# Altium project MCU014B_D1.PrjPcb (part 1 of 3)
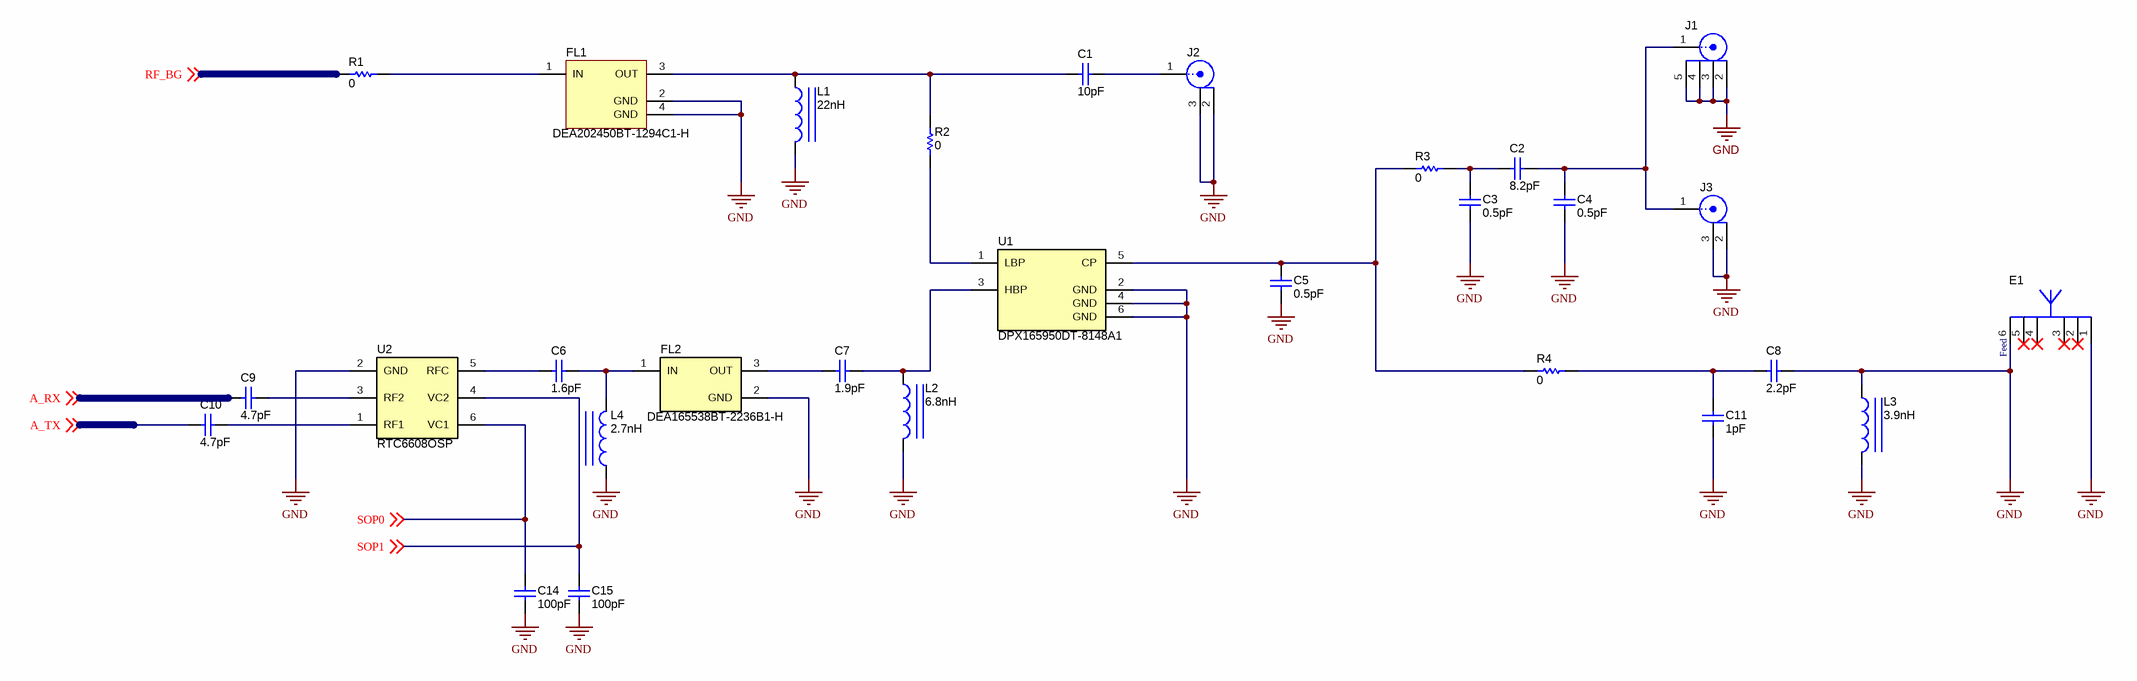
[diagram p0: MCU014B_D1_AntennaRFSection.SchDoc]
CopyrightYear: 2018; DrawnBy: Vince Rodriguez; PCB_Layout: Tessolve; PCB_Rev: B; PRJ_Customer: Public Release; PRJ_Engineer: Vince Rodriguez; PRJ_Number: MCU014; PRJ_Title: LAUNCHXL-CC3235(S & SF); SCH_Rev: B; TechSupport: http://www.ti.com/support; TID: N/A
7 sheets, 374 parts. Net scope: global (net labels, ports and power ports of the same name join across sheets).
Board file: MCU014B_D1.PcbDoc
Sheets:
  MCU014B_D1_AntennaRFSection.SchDoc
  MCU014B_D1_CoverSheet.SchDoc
  MCU014B_D1_EmulationCircuit.SchDoc
  MCU014B_D1_EVM_Hardware.SchDoc
  MCU014B_D1_EngineArea.SchDoc
  MCU014B_D1_HostInterface_ADC.SchDoc
  MCU014B_D1_PowerLedsSwitchSensors.SchDoc

## Sheet MCU014B_D1_AntennaRFSection.SchDoc
size 431 x 279 mm; Date: Not shown in title block; ApprovedBy: Not shown in title block; CheckedBy: Not shown in title block; Author: Not shown in title block; CompanyName: Not shown in title block; DrawnBy: Vince Rodriguez; Engineer: Vince Rodriguez; Organization: Not shown in title block; Address1: Not shown in title block; Address2: Not shown in title block; Address3: Not shown in title block; Address4: Not shown in title block; DocumentNumber: 6; Revision: Use project parameter SCH_Rev; SheetNumber: 6; SheetTotal: 7; PageSetup: Record=PageOptions¦CenterHorizontal=True¦CenterVertical=True¦PrintScale=1.00¦XCorrection=1.00¦YCorrection=1.00¦PrintKind=0¦BorderSize=5000000¦LeftOffset=0¦BottomOffset=0¦Orientation=2¦PaperLength=1000¦PaperWidth=1000¦Scale=100¦PaperSource=15¦PrintQuality=600¦MediaType=1¦DitherType=10¦PaperKind=Letter¦PrintScaleMode=1

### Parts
C1  ValueDisplayed: 10pF  [0402S]  (hidden comment: CMP-0006408-2)
C2  ValueDisplayed: 8.2pF  [0402S]  (hidden comment: 0402N8R2C500CT)
C3  ValueDisplayed: 0.5pF  [0402S]  (hidden comment: GJM1555C1HR50BB01J)
C4  ValueDisplayed: 0.5pF  [0402S]  (hidden comment: GJM1555C1HR50BB01J)
C5  ValueDisplayed: 0.5pF  [0402S]  (hidden comment: GJM1555C1HR50BB01J)
C6  ValueDisplayed: 1.6pF  [0201_033]  (hidden comment: GRM0335C1H1R6BA01D)
C7  ValueDisplayed: 1.9pF  [0402S]  (hidden comment: GJM1555C1H1R9WB01D)
C8  ValueDisplayed: 2.2pF  [0402S]  (hidden comment: GJM1555C1H2R2BB01D)
C9  ValueDisplayed: 4.7pF  [0201_033]  (hidden comment: GRM0335C1H4R7BA01D)
C10  ValueDisplayed: 4.7pF  [0201_033]  (hidden comment: GRM0335C1H4R7BA01D)
C11  ValueDisplayed: 1pF  [0402S]  (hidden comment: CMP-0006426-2)
C14  ValueDisplayed: 100pF  [0201]  (hidden comment: CC0201JRNPO8BN101)
C15  ValueDisplayed: 100pF  [0201]  (hidden comment: CC0201JRNPO8BN101)
E1  CMP-0001857-1  [Ethertronics_M830520]  (value not drawn)
FL1  PartNumber: DEA202450BT-1294C1-H  [TDK_DEA202450BT-1294C1-H]  (hidden comment: CMP-0002039-2)
FL2  PartNumber: DEA165538BT-2236B1-H  [TDK_DEA165538BT-2236B1-H]  (hidden comment: CMP-0002038-2)
J1  CMP-0055832-1  [Hustsan_SMA-10V21-TGG]  (value not drawn)
J2  U.FL-R-SMT-1(01)  [CONN_UFL-R-SMT-1]  (value not drawn)
J3  U.FL-R-SMT-1(01)  [CONN_UFL-R-SMT-1]  (value not drawn)
L1  ValueDisplayed: 22nH  [0402S]  (hidden comment: LQG15HZ22NH02D)
L2  ValueDisplayed: 6.8nH  [0402S]  (hidden comment: LQG15HZ6N8H02D)
L3  ValueDisplayed: 3.9nH  [0402S]  (hidden comment: CMP-0058633-2)
L4  ValueDisplayed: 2.7nH  [0402S]  (hidden comment: LQG15WH2N7C02D)
R1  ValueDisplayed: 0  [0201]  (hidden comment: CRCW02010000Z0ED)
R2  ValueDisplayed: 0  [0402S]  (hidden comment: CMP-0026992-2)
R3  ValueDisplayed: 0  [0402S]  (hidden comment: CMP-0026992-2)
R4  ValueDisplayed: 0  [0402S]  (hidden comment: CMP-0026992-2)
U1  PartNumber: DPX165950DT-8148A1  [TDK_DPX165950DT-8148A1]  (hidden comment: CMP-0002040-1)
U2  RTC6608OSP  [Richwave_RTC6608OSP]

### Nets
GND: C3.2 C4.2 C5.2 C8.2 C11.2 C14.2 C15.2 E1.1(Feed) E1.6 FL1.2(GND) FL1.4(GND) FL2.2(GND) J1.2 J1.3 J1.4 J1.5 J2.2 J2.3 J3.2 J3.3 L1.2 L2.2 L3.1 L3.2 L4.1 U1.2(GND) U1.4(GND) U1.6(GND) U2.2(GND)
A_RX: C9.2 ; off-sheet A_RX
A_TX: C10.2 ; off-sheet A_TX
RF_BG: R1.2 ; off-sheet RF_BG
SOP0: C14.1 U2.6(VC1) ; off-sheet SOP0
SOP1: C15.1 U2.4(VC2) ; off-sheet SOP1
NetC1_1: C1.1 FL1.3(OUT) L1.1 R2.2
NetC1_2: C1.2 J2.1
NetC2_1: C2.1 C3.1 R3.2
NetC2_2: C2.2 C4.1 J1.1 J3.1
NetC5_1: C5.1 R3.1 R4.1 U1.5(CP)
NetC6_1: C6.1 FL2.1(IN) L4.2
NetC6_2: C6.2 U2.5(RFC)
NetC7_1: C7.1 FL2.3(OUT)
NetC7_2: C7.2 L2.1 U1.3(HBP)
NetC8_1: C8.1 C11.1 R4.2
NetC9_1: C9.1 U2.3(RF2)
NetC10_1: C10.1 U2.1(RF1)
NetFL1_1: FL1.1(IN) R1.1
NetR2_1: R2.1 U1.1(LBP)

Not connected (* = marked no-connect by the designer): E1 2(GND)* 3(GND)* 4(Feed)* 5*

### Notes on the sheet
- (near E1) Feed

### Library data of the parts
C1 = CMP-0006408-2: CAP, CERM, 10 pF, 50 V, +/- 5%, C0G/NP0, 0402; PartNumber: GRM1555C1H100JA01D; Manufacturer: MuRata; Alternate Manufacturer: ----; Polarized: N; CompType: Capacitor; Value: 10pF; U/M: EA; Value1: Unknown; VDC_V: 50V; TaMin_C: -55°C; TaMax_C: 125°C; Cap_Case: 0402; SizeAreaWB_mm2: 3; SizeZ_mm: 0.6; SizeX_mm: 1; SizeY_mm: 0.5; AEC Category: Q200
C2 = CMP-0085845-1: CAP, CERM, 8.2 pF, 50 V,+/- 3%, C0G/NP0, 0402; Manufacturer: Walsin; Alternate PartNumber: GRM1555C1H8R2CA01D; Alternate Manufacturer: MuRata; Polarized: N; Value: 8.2pF; U/M: EA; VDC_V: 50V; TaMin_C: -55°C; TaMax_C: 125°C; Cap_Case: 0402; SizeArea_mm2: 0.5; SizeAreaWB_mm2: 3; SizeX_mm: 1; SizeZ_mm: 0.6; AEC Category: Q200
C3-C5 = CMP-0080073-1: CAP, CERM, 0.5 pF, 50 V,+/- 20%, C0G/NP0, 0402; Manufacturer: MuRata; Polarized: N; Value: 0.5pF; U/M: EA; VDC_V: 50V; TaMin_C: -55°C; TaMax_C: 125°C; Cap_Case: 0402; Green_Lifecycle: Active; SizeAreaWB_mm2: 3; Green_REACh: Passed; SizeZ_mm: 0.6; SizeX_mm: 1; SizeY_mm: 0.5; AEC Category: Q200
C6 = CMP-0080075-1: CAP, CERM, 1.6 pF, 50 V,+/- 7%, C0G/NP0, 0201; Manufacturer: MuRata; Polarized: N; Value: 1.6pF; U/M: EA; VDC_V: 50V; TaMin_C: -55°C; TaMax_C: 125°C; Cap_Case: 0201; SizeArea_mm2: 0.18; SizeAreaWB_mm2: 2.08; SizeX_mm: 0.6; SizeY_mm: 0.3; SizeZ_mm: 0.33; AEC Category: Q200
C7 = CMP-0085853-1: CAP, CERM, 1.9 pF, 50 V,+/- 2.6%, C0G/NP0, 0402; Manufacturer: MuRata; Alternate PartNumber: GRM1555C1H1R9WA01D; Polarized: N; Value: 1.9pF; U/M: EA; VDC_V: 50V; TaMin_C: -55°C; TaMax_C: 125°C; Cap_Case: 0402; SizeArea_mm2: 0.5; SizeAreaWB_mm2: 3; SizeX_mm: 1; SizeZ_mm: 0.6; AEC Category: Q200
C8 = CMP-0085854-1: CAP, CERM, 2.2 pF, 50 V,+/- 4.5%, C0G/NP0, 0402; Manufacturer: MuRata; Alternate PartNumber: GRM1555C1H2R2BA01D; Polarized: N; Value: 2.2pF; U/M: EA; VDC_V: 50V; TaMin_C: -55°C; TaMax_C: 125°C; Cap_Case: 0402; SizeArea_mm2: 0.5; SizeAreaWB_mm2: 3; SizeX_mm: 1; SizeZ_mm: 0.6; AEC Category: Q200
C9 C10 = CMP-0080076-1: CAP, CERM, 4.7 pF, 50 V,+/- 3%, C0G/NP0, 0201; Manufacturer: MuRata; Polarized: N; Value: 4.7pF; U/M: EA; VDC_V: 50V; TaMin_C: -55°C; TaMax_C: 125°C; Cap_Case: 0201; SizeArea_mm2: 0.18; SizeAreaWB_mm2: 2.08; SizeX_mm: 0.6; SizeY_mm: 0.3; SizeZ_mm: 0.33; AEC Category: Q200
C11 = CMP-0006426-2: CAP, CERM, 1 pF, 50 V, +/- 10%, C0G/NP0, 0402; PartNumber: GRM1555C1H1R0BA01D; Manufacturer: MuRata; Alternate PartNumber: ----; Polarized: N; CompType: Capacitor; Value: 1pF; U/M: EA; Value1: Unknown; VDC_V: 50V; TaMin_C: -55°C; TaMax_C: 125°C; Cap_Case: 0402; SizeAreaWB_mm2: 3; SizeZ_mm: 0.6; SizeX_mm: 1; SizeY_mm: 0.5; AEC Category: Q200
C14 C15 = CMP-0085847-1: CAP, CERM, 100 pF, 25 V,+/- 5%, C0G/NP0, 0201; Manufacturer: Yageo; Alternate PartNumber: C0603C0G1E101J030BA; Polarized: N; Value: 100pF; U/M: EA; VDC_V: 25V; TaMin_C: -55°C; TaMax_C: 125°C; SizeArea_mm2: 0.18; SizeAreaWB_mm2: 2.08; SizeX_mm: 0.6; SizeY_mm: 0.3; SizeZ_mm: 0.26; AEC Category: Q200
E1 = CMP-0001857-1: WLAN ANTENNA 802.11, SMD; PartNumber: M830520; Manufacturer: Ethertronics; Alternate Manufacturer: ----; SizeAreaWB_mm2: 50; SizeArea_mm2: 24; SizeX_mm: 3; SizeY_mm: 8; SizeZ_mm: 1.33
FL1 = CMP-0002039-2: Multilayer Chip Band Pass Filter For 2.4GHz W-LAN/Bluetooth, SMD; Manufacturer: TDK; Alternate Manufacturer: ----; Value: 1.02 dB
FL2 = CMP-0002038-2: Multilayer Band Pass Filter For 5GHz W-LAN/LTE-U; Manufacturer: TDK; Alternate Manufacturer: ----; SizeAreaWB_mm2: 4.68; SizeArea_mm2: 1.28; SizeX_mm: 1.6; SizeY_mm: 0.8; SizeZ_mm: 0.65
J1 = CMP-0055832-1: Connector, SMA, Vertical, Gold, SMT; PartNumber: SMA-10V21-TGG; Manufacturer: Hus-Tsan Group Co., Ltd.; Alternate Manufacturer: 傲创; Alternate PartNumber: SMA-050710; CT: TRUE; CNHeader: FALSE
J2 J3 = CMP-0075320-1: Receptacle, Ultra Miniature Coaxial, Male Pin, 50 ohm, SMT; Manufacturer: Hirose Electric Co. Ltd.; Alternate Manufacturer: ----; CNHeader: False; Gender: Female; ContactFinish: Gold
L1 = CMP-0080371-1: Inductor, Multilayer, Air Core, 22 nH, 0.35 A, 0.42 ohm, AEC-Q200 Grade 1, SMD; Manufacturer: MuRata; Value: 22nH; Imax_A: 350mA; Irms: 0.35A @ 25C rise; DCR_ohm: 0.42; Value2: 0.35A; SizeAreaWB_mm2: 3; SizeZ_mm: 0.55; SizeX_mm: 1; SizeY_mm: 0.5; AEC Qualified: Y; AEC Category: Q200
L2 = CMP-0080372-1: Inductor, Multilayer, Air Core, 6.8 nH, 0.6 A, 0.22 ohm, AEC-Q200 Grade 1, SMD; Manufacturer: MuRata; Value: 6.8nH; Imax_A: 600mA; Irms: 0.6A @ 25C rise; DCR_ohm: 0.22; Value2: 0.6A; SizeAreaWB_mm2: 3; SizeZ_mm: 0.55; SizeX_mm: 1; SizeY_mm: 0.5; AEC Qualified: Y; AEC Category: Q200
L3 = CMP-0058633-2: Inductor, Multilayer, Air Core, 3.9 nH, 0.75 A, 0.14 ohm, SMD; PartNumber: LQG15HS3N9S02D; Manufacturer: MuRata; Value: 3.9nH; Imax_A: 750mA; Irms: 0.75A @ 25C rise; DCR_ohm: 0.14; Value2: 0.75A; Green_Lifecycle: Active; SizeAreaWB_mm2: 3; Green_REACh: Passed; SizeZ_mm: 0.55; SizeX_mm: 1; SizeY_mm: 0.5; AEC Qualified: N; AEC Category: Q200
L4 = CMP-0080374-1: Inductor, Multilayer, Air Core, 2.7 nH, 0.9 A, 0.07 ohm, AEC-Q200 Grade 1, SMD; Manufacturer: MuRata; Value: 2.7nH; Imax_A: 900mA; Irms: 0.9A @ 25C rise; DCR_ohm: 0.07; Value2: 0.9A; SizeAreaWB_mm2: 3.2; SizeZ_mm: 0.6; SizeX_mm: 1; AEC Qualified: Y; AEC Category: Q200
R1 = CMP-0027008-4: RES, 0, 5%, 0.05 W, 0201; Manufacturer: Vishay-Dale; Value: 0; Value_Code: 0000; Power_W: 50mW; Value2: 0.05W; TempCo: ppm/C; SizeArea_mm2: 0.18; SizeX_mm: 0.6; SizeY_mm: 0.3; SizeZ_mm: 0.26; EIA_Code: E24; AEC Category: Q200; AEC Qualified: N
R2-R4 = CMP-0026992-2: RES, 0, 5%, 0.063 W, 0402; PartNumber: ERJ-2GE0R00X; Manufacturer: Panasonic; Alternate Manufacturer: YAGEO; Alternate PartNumber: RC0402JR-070RL; CompType: Resistor; Value: 0; Value_Code: 0000; Power_W: 63mW; Value2: 0.063W; VDC_V: 50V; TempCo: 600 ppm/C; SizeArea_mm2: 0.5; SizeX_mm: 1; SizeZ_mm: 0.6; EIA_Code: E24; U/M: EA; AEC Category: Q200
U1 = CMP-0002040-1: Multilayer Diplexer for 2.4GHz W-LAN & Bluetooth / 5GHz W-LAN; Manufacturer: TDK; Alternate Manufacturer: ----; SizeAreaWB_mm2: 4.68; SizeArea_mm2: 1.28; SizeX_mm: 0.8; SizeY_mm: 1.6; SizeZ_mm: 0.7
U2 = CMP-0065464-1: 0.03 GHz-6 GHz SPDT Switch; Manufacturer: Richwave; Alternate Manufacturer: ----; Alternate PartNumber: Order Directly from Richwave; SizeAreaWB_mm2: 4.0; SizeArea_mm2: 1.0; SizeZ_mm: 0.4

## Sheet MCU014B_D1_CoverSheet.SchDoc
size 558 x 431 mm; Date: Not shown in title block; ApprovedBy: Not shown in title block; CheckedBy: Not shown in title block; Author: Not shown in title block; CompanyName: Not shown in title block; DrawnBy: Vince Rodriguez; Engineer: Vince Rodriguez; Organization: Not shown in title block; Address1: Not shown in title block; Address2: Not shown in title block; Address3: Not shown in title block; Address4: Not shown in title block; DocumentNumber: 1; Revision: Use project parameter SCH_Rev; SheetNumber: 1; SheetTotal: 7; PageSetup: Record=PageOptions¦CenterHorizontal=True¦CenterVertical=True¦PrintScale=1.00¦XCorrection=1.00¦YCorrection=1.00¦PrintKind=0¦BorderSize=5000000¦LeftOffset=0¦BottomOffset=0¦Orientation=2¦PaperLength=1000¦PaperWidth=1000¦Scale=100¦PaperSource=15¦PrintQuality=600¦MediaType=1¦DitherType=10¦PaperKind=Letter¦PrintScaleMode=1
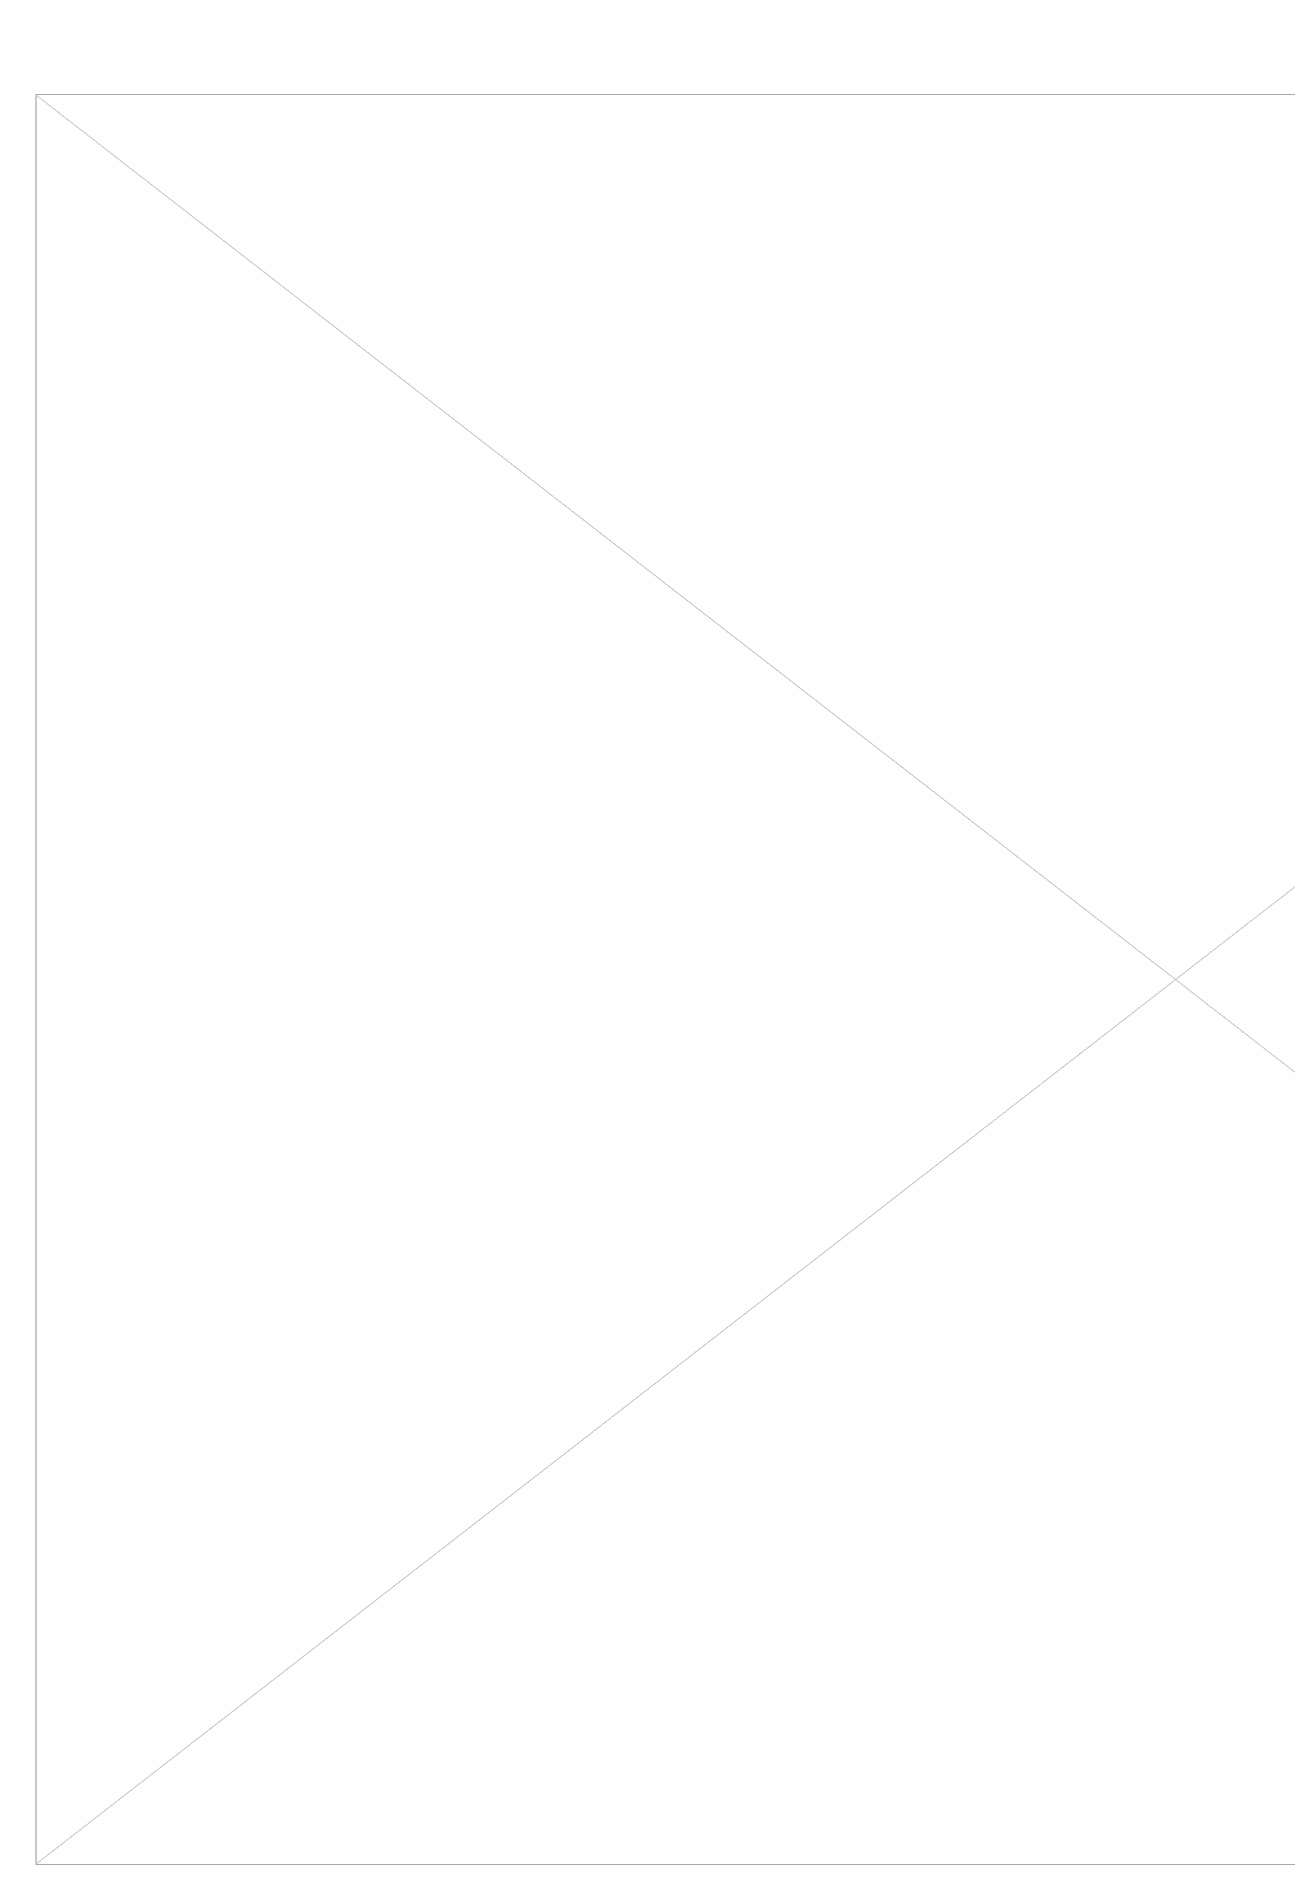
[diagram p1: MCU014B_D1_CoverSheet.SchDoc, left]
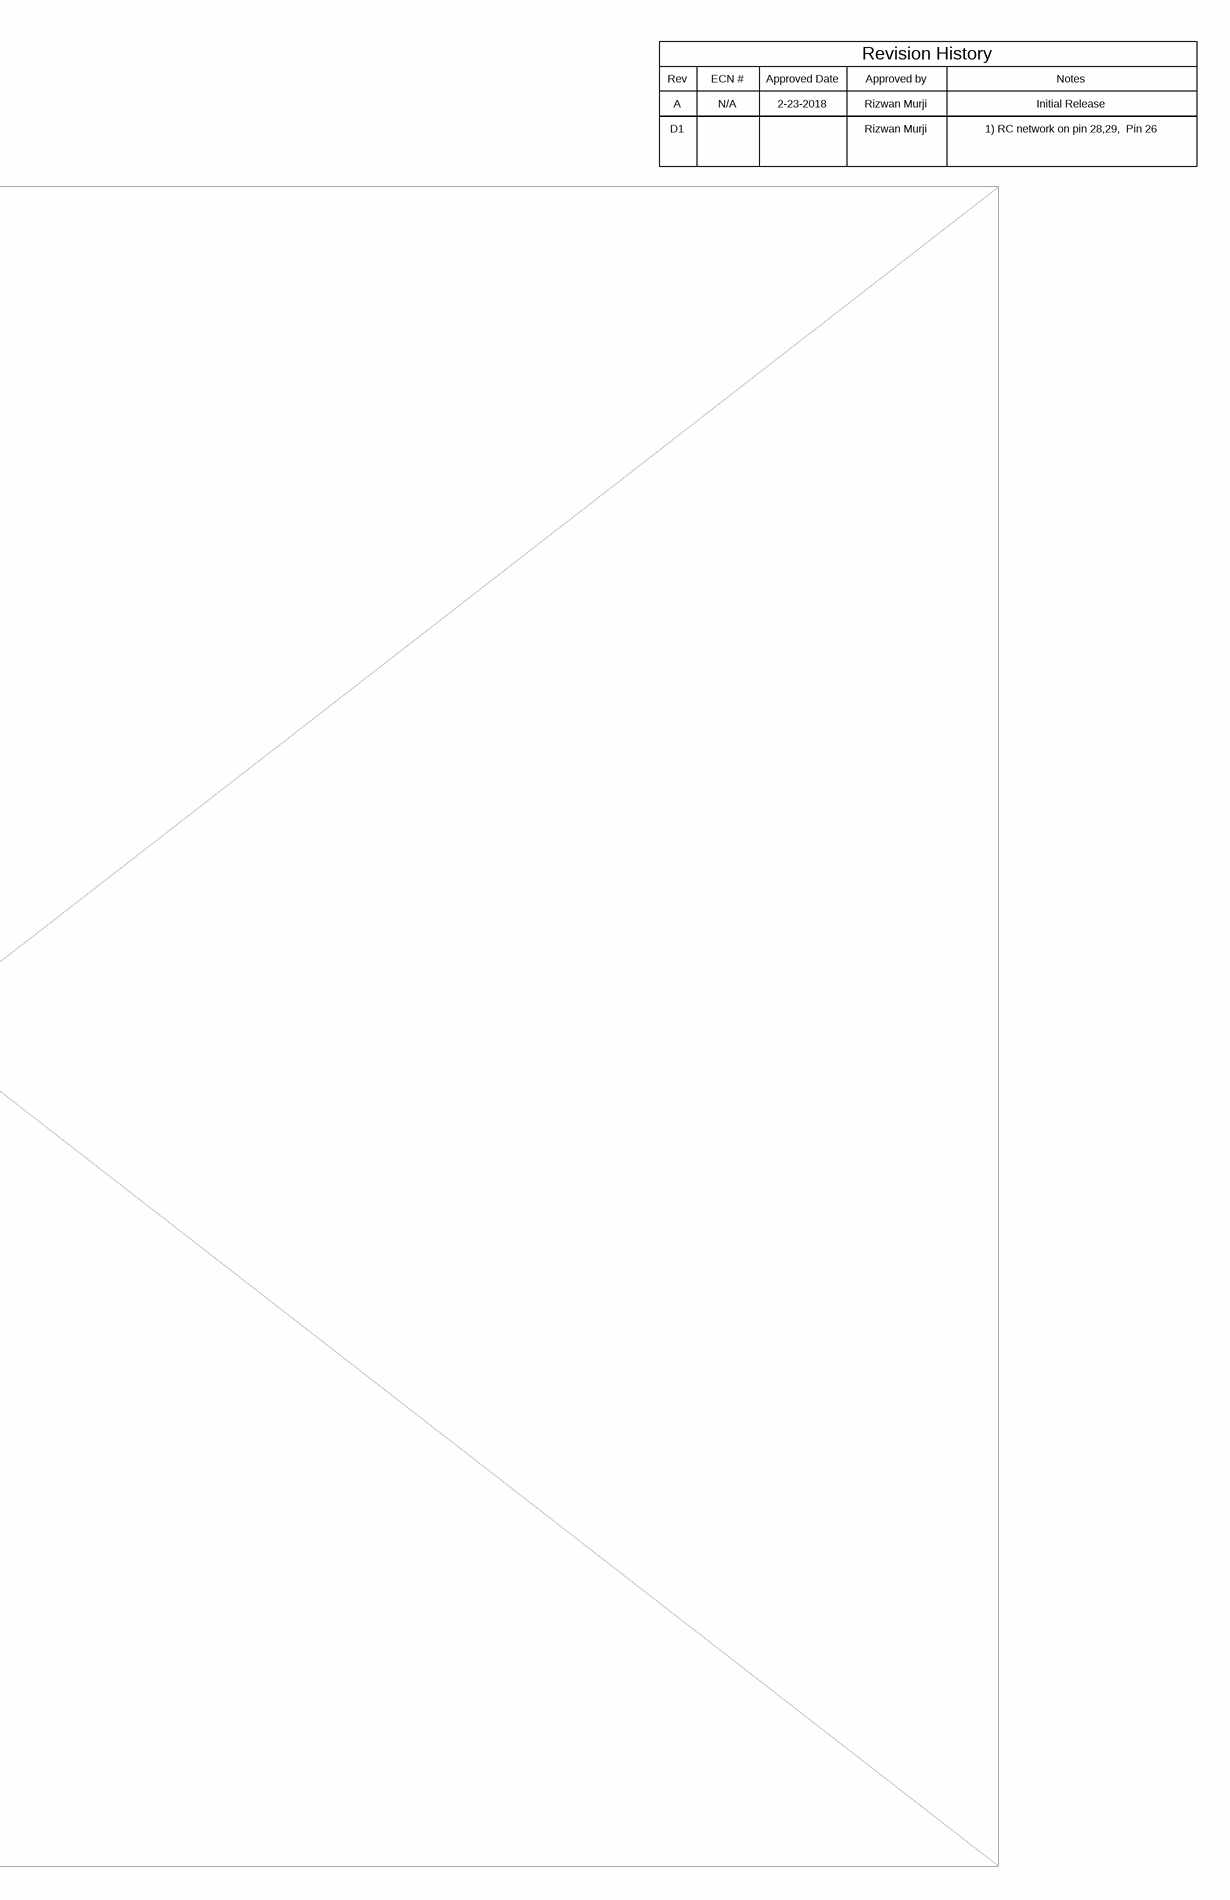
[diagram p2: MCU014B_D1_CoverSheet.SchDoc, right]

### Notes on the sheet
- Rev
- ECN #
- Approved Date
- Approved by
- Revision History
- Notes
- A
- D1
- N/A
- 2-23-2018
- Rizwan Murji
- Initial Release
- 1) RC network on pin 28,29,  Pin 26

## Sheet MCU014B_D1_EmulationCircuit.SchDoc
size 558 x 431 mm; Date: Not shown in title block; ApprovedBy: Not shown in title block; CheckedBy: Not shown in title block; Author: Not shown in title block; CompanyName: Not shown in title block; DrawnBy: Vince Rodriguez; Engineer: Not shown in title block; Organization: Not shown in title block; Address1: Not shown in title block; Address2: Not shown in title block; Address3: Not shown in title block; Address4: Not shown in title block; DocumentNumber: 2; Revision: Use project parameter SCH_Rev; SheetNumber: 2; SheetTotal: 7; PageSetup: Record=PageOptions¦CenterHorizontal=True¦CenterVertical=True¦PrintScale=1.00¦XCorrection=1.00¦YCorrection=1.00¦PrintKind=0¦BorderSize=5000000¦LeftOffset=0¦BottomOffset=0¦Orientation=2¦PaperLength=1000¦PaperWidth=1000¦Scale=100¦PaperSource=15¦PrintQuality=600¦MediaType=1¦DitherType=10¦PaperKind=Letter¦PrintScaleMode=1
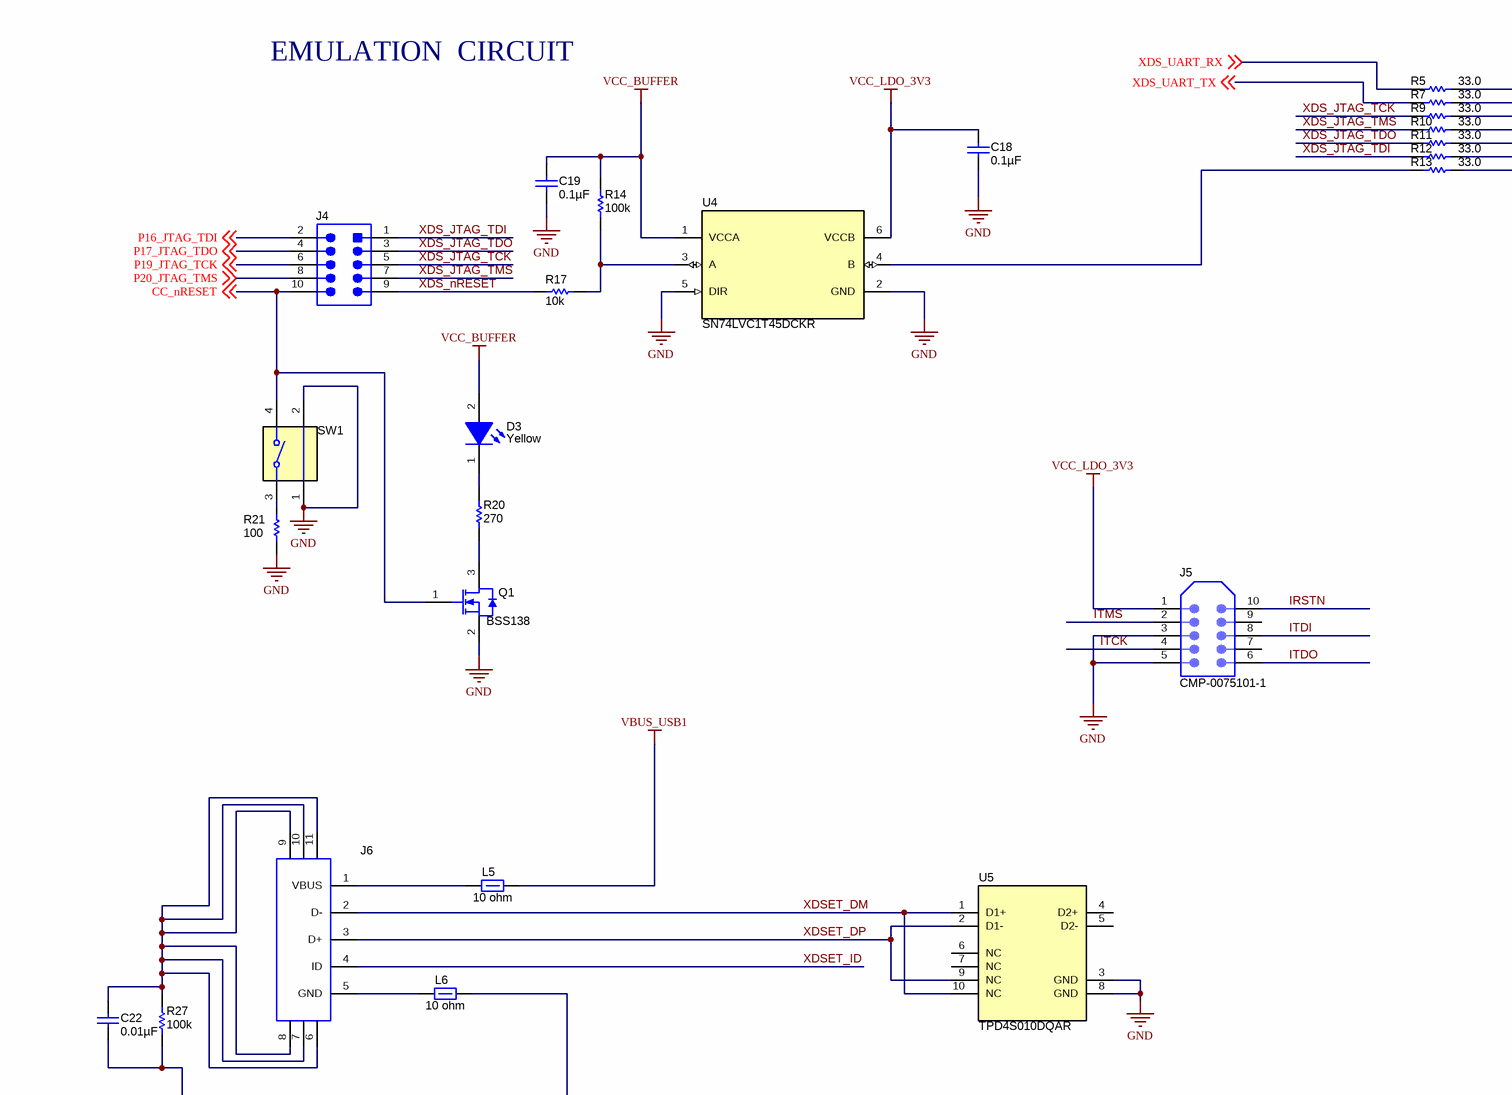
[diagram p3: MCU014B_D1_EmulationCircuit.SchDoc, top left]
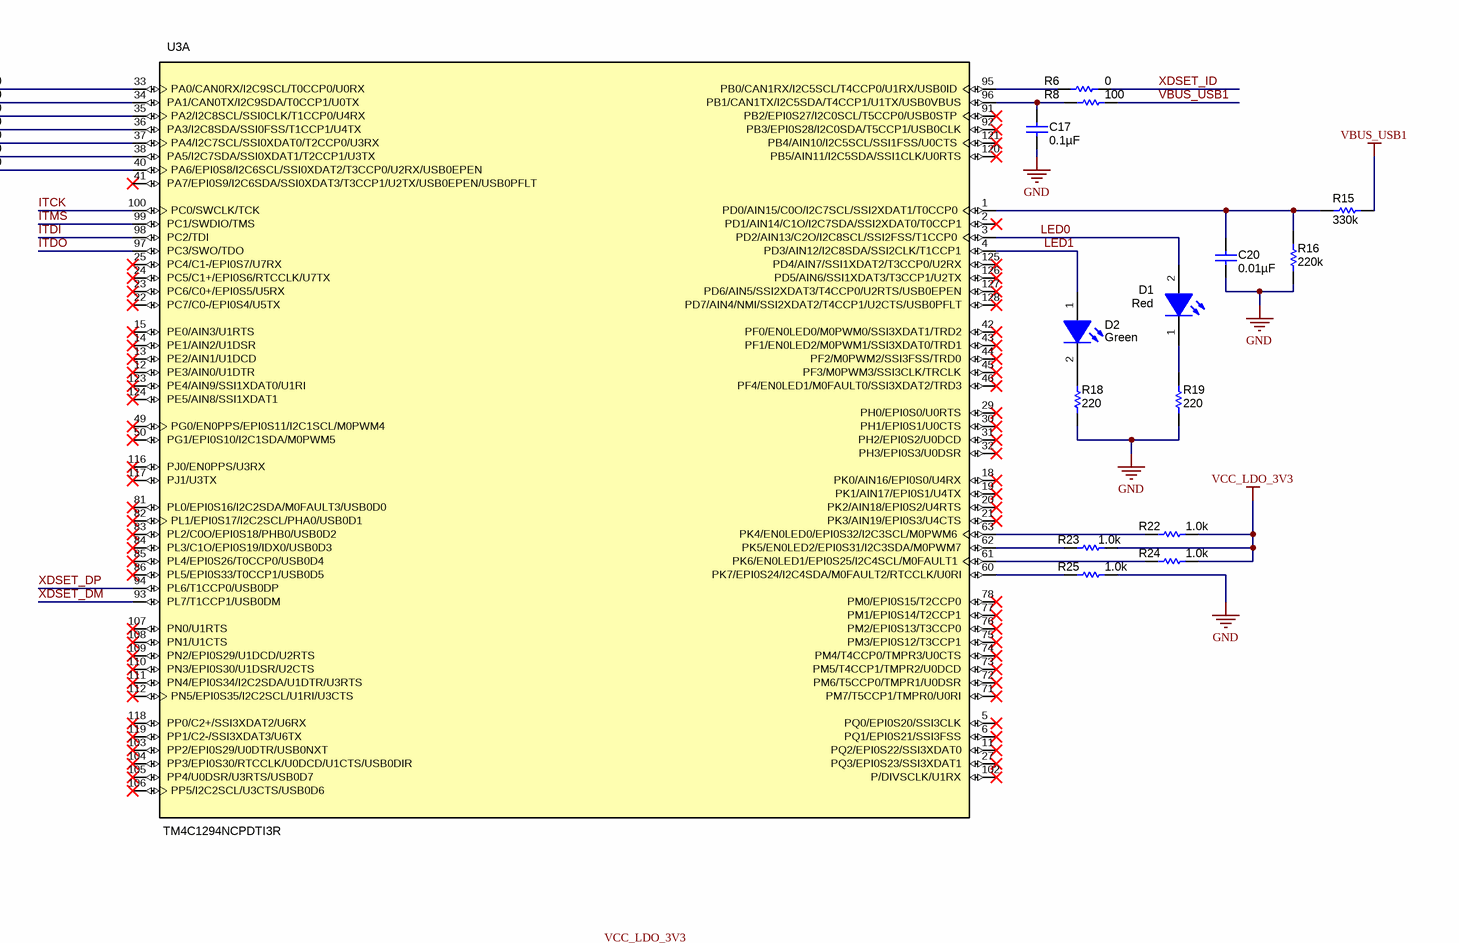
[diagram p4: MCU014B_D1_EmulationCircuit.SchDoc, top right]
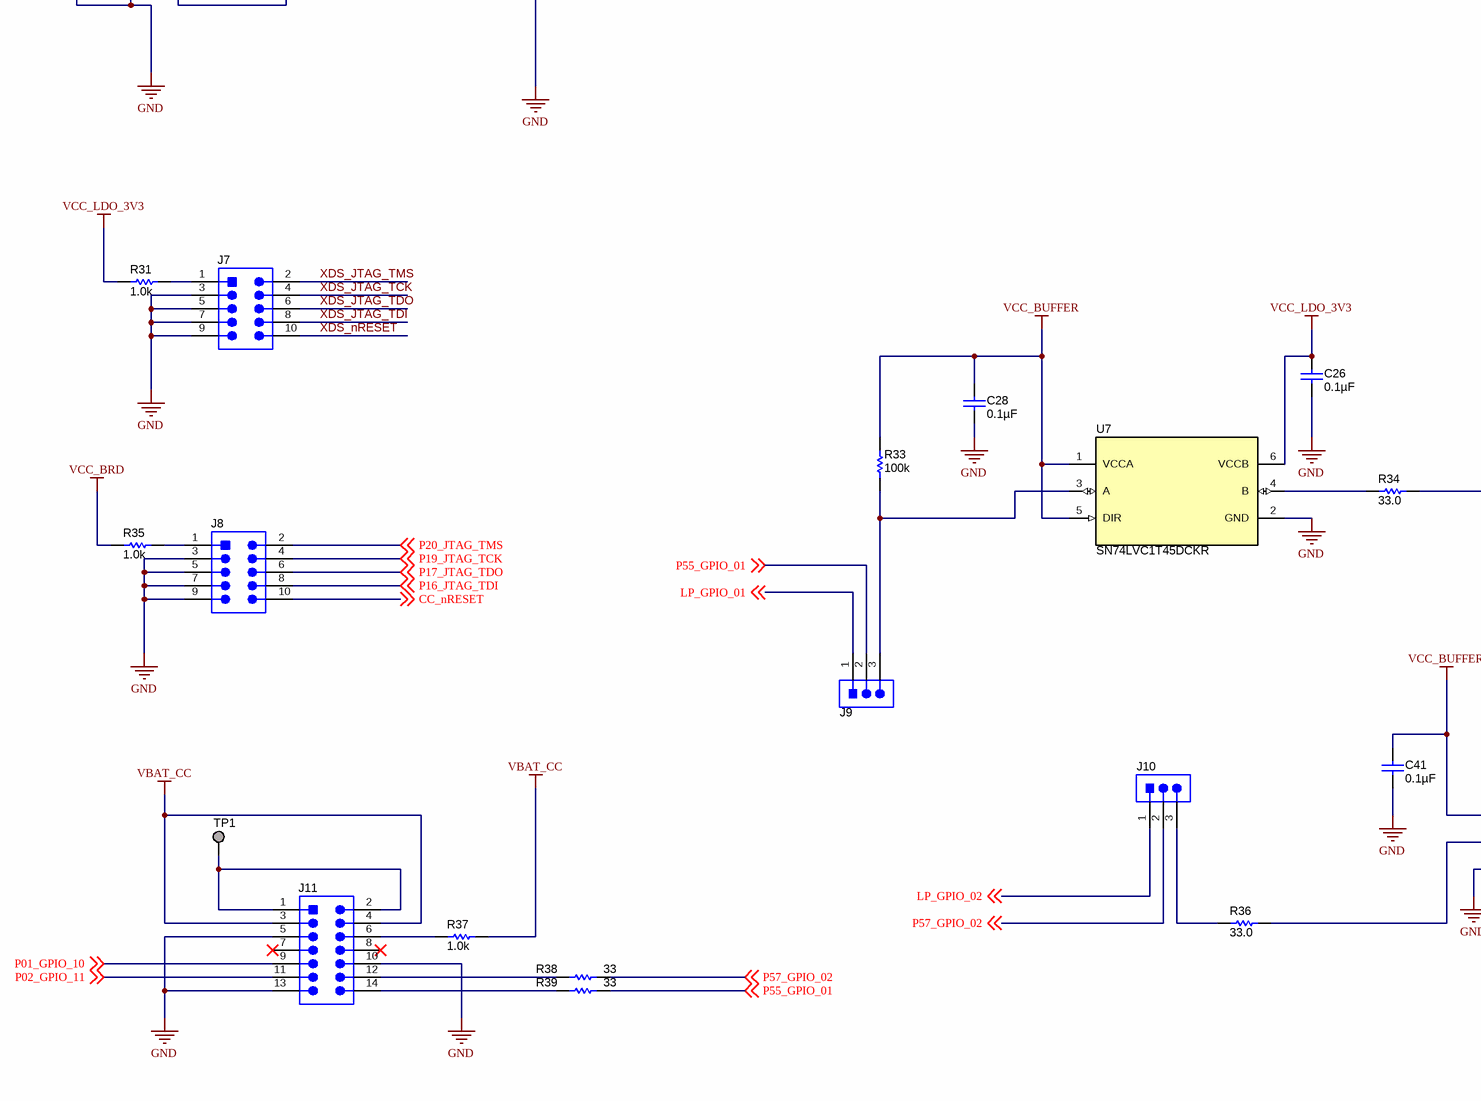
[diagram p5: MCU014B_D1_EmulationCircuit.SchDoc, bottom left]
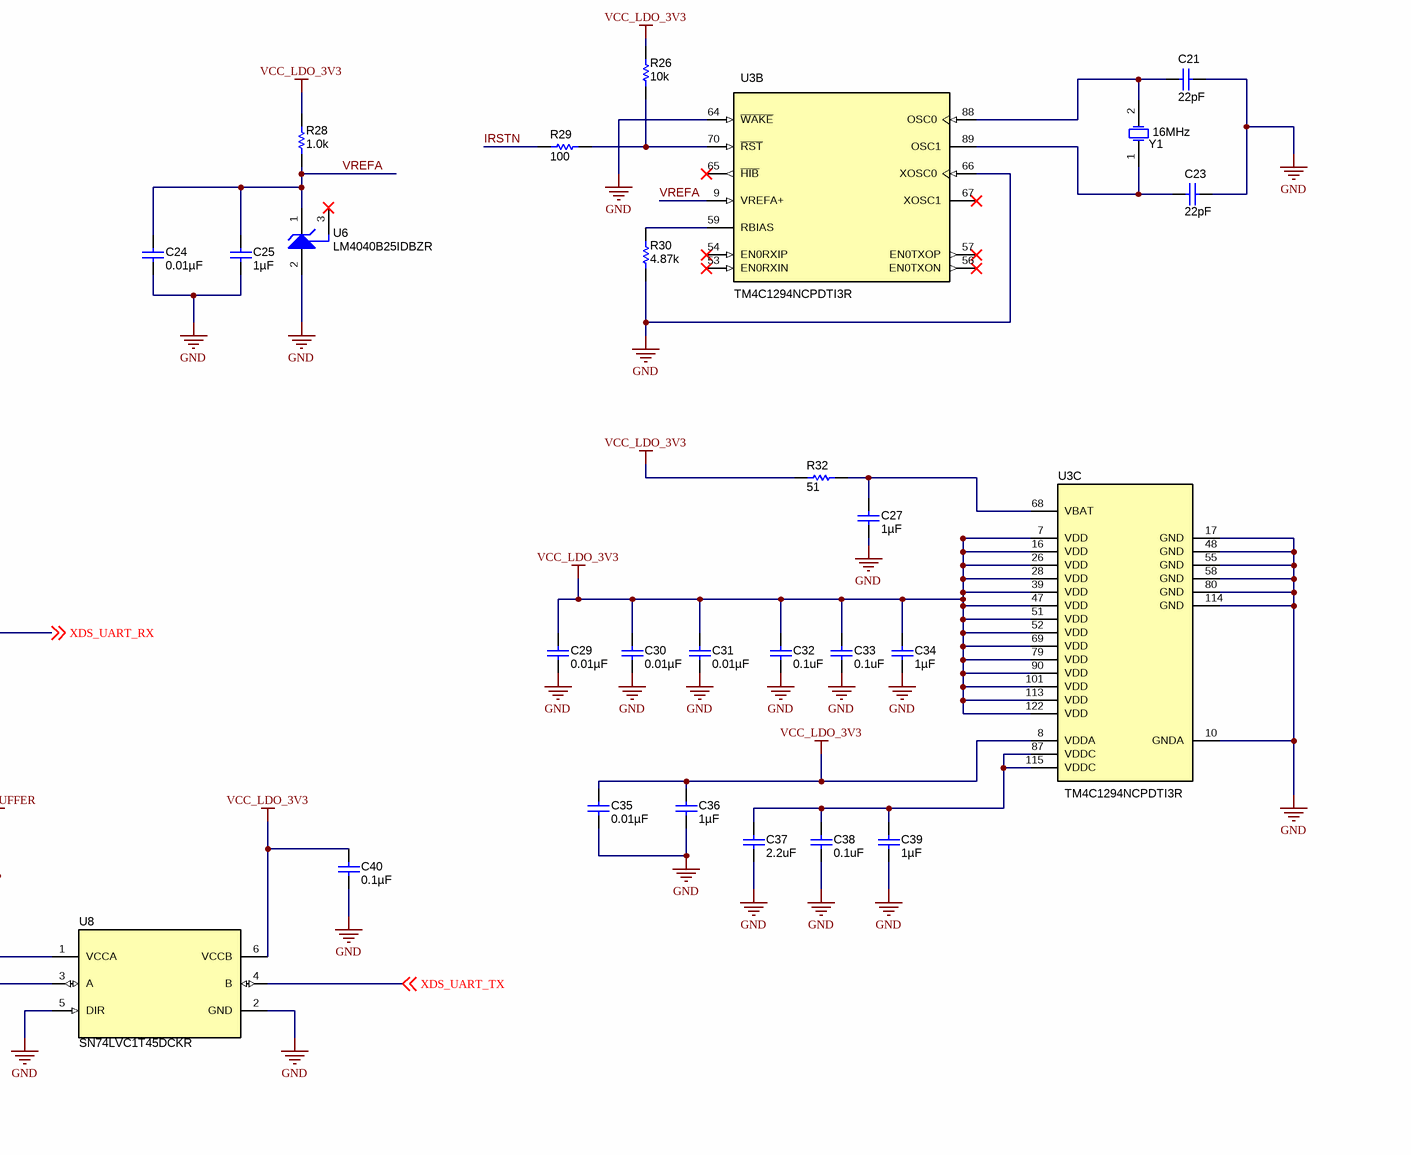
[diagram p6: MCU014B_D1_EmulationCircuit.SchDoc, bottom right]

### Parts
C17  ValueDisplayed: 0.1µF  [0402S]  (hidden comment: CL05B104KO5NNNC)
C18  ValueDisplayed: 0.1µF  [0402S]  (hidden comment: CL05B104KO5NNNC)
C19  ValueDisplayed: 0.1µF  [0402S]  (hidden comment: CL05B104KO5NNNC)
C20  ValueDisplayed: 0.01µF  [0402S]  (hidden comment: 0402B103K500CT)
C21  ValueDisplayed: 22pF  [0402S]  (hidden comment: CL05C220JB5NNNC)
C22  ValueDisplayed: 0.01µF  [0402S]  (hidden comment: 0402B103K500CT)
C23  ValueDisplayed: 22pF  [0402S]  (hidden comment: CL05C220JB5NNNC)
C24  ValueDisplayed: 0.01µF  [0402S]  (hidden comment: 0402B103K500CT)
C25  ValueDisplayed: 1µF  [0402S]  (hidden comment: CL05A105KA5NQNC)
C26  ValueDisplayed: 0.1µF  [0402S]  (hidden comment: CL05B104KO5NNNC)
C27  ValueDisplayed: 1µF  [0402S]  (hidden comment: CL05A105KA5NQNC)
C28  ValueDisplayed: 0.1µF  [0402S]  (hidden comment: CL05B104KO5NNNC)
C29  ValueDisplayed: 0.01µF  [0402S]  (hidden comment: 0402B103K500CT)
C30  ValueDisplayed: 0.01µF  [0402S]  (hidden comment: 0402B103K500CT)
C31  ValueDisplayed: 0.01µF  [0402S]  (hidden comment: 0402B103K500CT)
C32  ValueDisplayed: 0.1uF  [0603]  (hidden comment: CMP-0006758-5)
C33  ValueDisplayed: 0.1uF  [0603]  (hidden comment: CMP-0006758-5)
C34  ValueDisplayed: 1µF  [0402S]  (hidden comment: CL05A105KA5NQNC)
C35  ValueDisplayed: 0.01µF  [0402S]  (hidden comment: 0402B103K500CT)
C36  ValueDisplayed: 1µF  [0402S]  (hidden comment: CL05A105KA5NQNC)
C37  ValueDisplayed: 2.2uF  [0402]  (hidden comment: CMP-0006275-2)
C38  ValueDisplayed: 0.1uF  [0603]  (hidden comment: CMP-0006758-5)
C39  ValueDisplayed: 1µF  [0402S]  (hidden comment: CL05A105KA5NQNC)
C40  ValueDisplayed: 0.1µF  [0402S]  (hidden comment: CL05B104KO5NNNC)
C41  ValueDisplayed: 0.1µF  [0402S]  (hidden comment: CL05B104KO5NNNC)
D1  value Red  [SML-31_Red]  (hidden comment: CMP-0002871-1)
D2  value Green  [LED_SML-LX0603GW]  (hidden comment: CMP-0002834-1)
D3  value Yellow  [WL-SMCW_YELLOW]  (hidden comment: CMP-0002892-2)
J4  CMP-0054806-2  [WURTH_61301021121]  (value not drawn)
J5  CMP-0075101-1  [Tag_TC2050-NL]  (no BOM)
J6  CMP-0055311-1  [Molex_1051640001]  (value not drawn)
J7  CMP-0075533-1  [Samtec_FTSH-105-01-x-D-K]  (value not drawn)
J8  CMP-0075533-1  [Samtec_FTSH-105-01-x-D-K]  (value not drawn)
J9  CMP-0054796-1  [WURTH_61300311121]  (value not drawn)
J10  CMP-0054796-1  [WURTH_61300311121]  (value not drawn)
J11  CMP-0055564-1  [Samtec_FTSH-107-01-x-DV]  (value not drawn)
L5  ValueDisplayed: 10 ohm  [0402]  (hidden comment: CMP-0003309-1)
L6  ValueDisplayed: 10 ohm  [0402]  (hidden comment: CMP-0003309-1)
Q1  PartNumber: BSS138  [SOT-23]  (hidden comment: CMP-0000755-1)
R5  ValueDisplayed: 33.0  [0402]  (hidden comment: CMP-0026696-1)
R6  ValueDisplayed: 0  [0402]  (hidden comment: CMP-0026992-2)
R7  ValueDisplayed: 33.0  [0402]  (hidden comment: CMP-0026696-1)
R8  ValueDisplayed: 100  [0402]  (hidden comment: CMP-0026824-3)
R9  ValueDisplayed: 33.0  [0402]  (hidden comment: CMP-0026696-1)
R10  ValueDisplayed: 33.0  [0402]  (hidden comment: CMP-0026696-1)
R11  ValueDisplayed: 33.0  [0402]  (hidden comment: CMP-0026696-1)
R12  ValueDisplayed: 33.0  [0402]  (hidden comment: CMP-0026696-1)
R13  ValueDisplayed: 33.0  [0402]  (hidden comment: CMP-0026696-1)
R14  ValueDisplayed: 100k  [0402]  (hidden comment: CMP-0026823-3)
R15  ValueDisplayed: 330k  [0402]  (hidden comment: CMP-0026905-2)
R16  ValueDisplayed: 220k  [0402]  (hidden comment: CMP-0026877-2)
R17  ValueDisplayed: 10k  [0402]  (hidden comment: CMP-0026825-5)
R18  ValueDisplayed: 220  [0603]  (hidden comment: CMP-0025756-4)
R19  ValueDisplayed: 220  [0603]  (hidden comment: CMP-0025756-4)
R20  ValueDisplayed: 270  [0603]  (hidden comment: CMP-0025765-4)
R21  ValueDisplayed: 100  [0402]  (hidden comment: CMP-0026656-1)
R22  ValueDisplayed: 1.0k  [0402]  (hidden comment: CMP-0026852-3)
R23  ValueDisplayed: 1.0k  [0402]  (hidden comment: CMP-0026852-3)
R24  ValueDisplayed: 1.0k  [0402]  (hidden comment: CMP-0026852-3)
R25  ValueDisplayed: 1.0k  [0402]  (hidden comment: CMP-0026852-3)
R26  ValueDisplayed: 10k  [0402]  (hidden comment: CMP-0026825-5)
R27  ValueDisplayed: 100k  [0603]  (hidden comment: CMP-0025698-4)
R28  ValueDisplayed: 1.0k  [0402]  (hidden comment: CMP-0026852-3)
R29  ValueDisplayed: 100  [0402]  (hidden comment: CMP-0025951-3)
R30  ValueDisplayed: 4.87k  [0603]  (hidden comment: CMP-0022457-4)
R31  ValueDisplayed: 1.0k  [0402]  (hidden comment: CMP-0026852-3)
R32  ValueDisplayed: 51  [0402]  (hidden comment: CMP-0026946-3)
R33  ValueDisplayed: 100k  [0402]  (hidden comment: CMP-0026823-3)
R34  ValueDisplayed: 33.0  [0402]  (hidden comment: CMP-0026696-1)
R35  ValueDisplayed: 1.0k  [0402]  (hidden comment: CMP-0026852-3)
R36  ValueDisplayed: 33.0  [0402]  (hidden comment: CMP-0026696-1)
R37  ValueDisplayed: 1.0k  [0402]  (hidden comment: CMP-0026852-3)
R38  ValueDisplayed: 33  [0603]  (hidden comment: CMP-0025787-4)
R39  ValueDisplayed: 33  [0603]  (hidden comment: CMP-0025787-4)
SW1  CMP-0002328-1  [SW_1188E]  (value not drawn)
TP1  CMP-0078143-2  [TESTPOINT]  (value not drawn)  (no BOM)
U3  PartNumber: TM4C1294NCPDTI3R  [PDT0128A]  (hidden comment: CMP-0029864-2)  (parts A,B,C of 3)
U4  PartNumber: SN74LVC1T45DCKR  [DCK0006A_N]  (hidden comment: CMP-0051039-3)
U5  PartNumber: TPD4S010DQAR  [DQA0010A]  (hidden comment: CMP-0043121-2)
U6  PartNumber: LM4040B25IDBZR  [DBZ0003A_N]  (hidden comment: CMP-0033095-1)
U7  PartNumber: SN74LVC1T45DCKR  [DCK0006A_N]  (hidden comment: CMP-0051039-3)
U8  PartNumber: SN74LVC1T45DCKR  [DCK0006A_N]  (hidden comment: CMP-0051039-3)
Y1  Frequency_Fixed: 16MHz  [XTAL_ABM3]  (hidden comment: CMP-0004648-3)

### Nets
GND: C17.2 C18.2 C19.2 C20.2 C21.1 C22.2 C23.1 C24.2 C25.2 C26.2 C27.2 C28.2 C29.2 C30.2 C31.2 C32.2 C33.2 C34.2 C35.2 C36.2 C37.2 C38.2 C39.2 C40.2 C41.2 J5.3 J5.5 J7.3 J7.5 J7.7 J7.9 J8.3 J8.5 J8.7 J8.9 J11.5 J11.10 J11.13 L6.2 Q1.2(S) R16.1 R18.1 R19.1 R21.1 R25.1 R27.1 R30.1 SW1.1 SW1.2 U3.10(GNDA) U3.17(GND) U3.48(GND) U3.55(GND) U3.58(GND) U3.64(~{WAKE}) U3.66(XOSC0) U3.80(GND) U3.114(GND) U4.2(GND) U4.5(DIR) U5.3(GND) U5.8(GND) U6.2(ANODE) U7.2(GND) U8.2(GND) U8.5(DIR)
VBAT_CC: J11.3 J11.4 R37.2
VBUS_USB1: L5.2 R8.1 R15.1
VCC_BRD: R35.1
VCC_BUFFER: C19.1 C28.1 C41.1 D3.2(A) R14.1 R33.1 U4.1(VCCA) U7.1(VCCA) U7.5(DIR) U8.1(VCCA)
VCC_LDO_3V3: C18.1 C26.1 C29.1 C30.1 C31.1 C32.1 C33.1 C34.1 C35.1 C36.1 C40.1 J5.1 R22.1 R23.1 R24.1 R26.1 R28.2 R31.1 R32.1 U3.7(VDD) U3.8(VDDA) U3.16(VDD) U3.26(VDD) U3.28(VDD) U3.39(VDD) U3.47(VDD) U3.51(VDD) U3.52(VDD) U3.69(VDD) U3.79(VDD) U3.90(VDD) U3.101(VDD) U3.113(VDD) U3.122(VDD) U4.6(VCCB) U7.6(VCCB) U8.6(VCCB)
CC_nRESET: J4.10 J8.10 Q1.1(G) SW1.4 ; off-sheet CC_nRESET
IRSTN: J5.10 R29.1
ITCK: J5.4 U3.100(PC0/SWCLK/TCK)
ITDI: J5.8 U3.98(PC2/TDI)
ITDO: J5.6 U3.97(PC3/SWO/TDO)
ITMS: J5.2 U3.99(PC1/SWDIO/TMS)
LED0: D1.2(A) U3.3(PD2/AIN13/C2O/I2C8SCL/SSI2FSS/T1CCP0)
LED1: D2.1(A) U3.4(PD3/AIN12/I2C8SDA/SSI2CLK/T1CCP1)
LP_GPIO_01: J9.1 ; off-sheet LP_GPIO_01
LP_GPIO_02: J10.1 ; off-sheet LP_GPIO_02
P01_GPIO_10: J11.9 ; off-sheet P01_GPIO_10
P02_GPIO_11: J11.11 ; off-sheet P02_GPIO_11
P16_JTAG_TDI: J4.2 J8.8 ; off-sheet P16_JTAG_TDI
P17_JTAG_TDO: J4.4 J8.6 ; off-sheet P17_JTAG_TDO
P19_JTAG_TCK: J4.6 J8.4 ; off-sheet P19_JTAG_TCK
P20_JTAG_TMS: J4.8 J8.2 ; off-sheet P20_JTAG_TMS
P55_GPIO_01: J9.2 R39.1 ; off-sheet P55_GPIO_01
P57_GPIO_02: J10.2 R38.1 ; off-sheet P57_GPIO_02
VREFA: C24.1 C25.1 R28.1 U3.9(VREFA+) U6.1(CATHODE)
XDS_JTAG_TCK: J4.5 J7.4 R9.1
XDS_JTAG_TDI: J4.1 J7.8 R12.1
XDS_JTAG_TDO: J4.3 J7.6 R11.1
XDS_JTAG_TMS: J4.7 J7.2 R10.1
XDS_nRESET: J4.9 J7.10 R17.1
XDS_UART_RX: R5.1 R34.2 ; off-sheet XDS_UART_RX
XDS_UART_TX: R7.1 U8.4(B) ; off-sheet XDS_UART_TX
XDSET_DM: J6.2(D-) U3.93(PL7/T1CCP1/USB0DM) U5.1(D1+) U5.10(NC)
XDSET_DP: J6.3(D+) U3.94(PL6/T1CCP0/USB0DP) U5.2(D1-) U5.9(NC)
XDSET_ID: J6.4(ID) R6.1
NetC17_1: C17.1 R8.2 U3.96(PB1/CAN1TX/I2C5SDA/T4CCP1/U1TX/USB0VBUS)
NetC20_1: C20.1 R15.2 R16.2 U3.1(PD0/AIN15/C0O/I2C7SCL/SSI2XDAT1/T0CCP0)
NetC21_2: C21.2 U3.88(OSC0) Y1.2(OSC2)
NetC22_1: C22.1 J6.6 J6.7 J6.8 J6.9 J6.10 J6.11 R27.2
NetC23_2: C23.2 U3.89(OSC1) Y1.1(OSC1)
NetC27_1: C27.1 R32.2 U3.68(VBAT)
NetC37_1: C37.1 C38.1 C39.1 U3.87(VDDC) U3.115(VDDC)
NetD1_1: D1.1(K) R19.2
NetD2_2: D2.2(K) R18.2
NetD3_1: D3.1(K) R20.2
NetJ6_1: J6.1(VBUS) L5.1
NetJ6_5: J6.5(GND) L6.1
NetJ7_1: J7.1 R31.2
NetJ8_1: J8.1 R35.2
NetJ9_3: J9.3 R33.2 U7.3(A)
NetJ10_3: J10.3 R36.1
NetJ11_1: J11.1 J11.2 TP1.1
NetJ11_6: J11.6 R37.1
NetJ11_12: J11.12 R38.2
NetJ11_14: J11.14 R39.2
NetQ1_3: Q1.3(D) R20.1
NetR5_2: R5.2 U3.33(PA0/CAN0RX/I2C9SCL/T0CCP0/U0RX)
NetR6_2: R6.2 U3.95(PB0/CAN1RX/I2C5SCL/T4CCP0/U1RX/USB0ID)
NetR7_2: R7.2 U3.34(PA1/CAN0TX/I2C9SDA/T0CCP1/U0TX)
NetR9_2: R9.2 U3.35(PA2/I2C8SCL/SSI0CLK/T1CCP0/U4RX)
NetR10_2: R10.2 U3.36(PA3/I2C8SDA/SSI0FSS/T1CCP1/U4TX)
NetR11_2: R11.2 U3.37(PA4/I2C7SCL/SSI0XDAT0/T2CCP0/U3RX)
NetR12_2: R12.2 U3.38(PA5/I2C7SDA/SSI0XDAT1/T2CCP1/U3TX)
NetR13_1: R13.1 U4.4(B)
NetR13_2: R13.2 U3.40(PA6/EPI0S8/I2C6SCL/SSI0XDAT2/T3CCP0/U2RX/USB0EPEN)
NetR14_2: R14.2 R17.2 U4.3(A)
NetR21_2: R21.2 SW1.3
NetR22_2: R22.2 U3.63(PK4/EN0LED0/EPI0S32/I2C3SCL/M0PWM6)
NetR23_2: R23.2 U3.62(PK5/EN0LED2/EPI0S31/I2C3SDA/M0PWM7)
NetR24_2: R24.2 U3.61(PK6/EN0LED1/EPI0S25/I2C4SCL/M0FAULT1)
NetR25_2: R25.2 U3.60(PK7/EPI0S24/I2C4SDA/M0FAULT2/RTCCLK/U0RI)
NetR26_2: R26.2 R29.2 U3.70(~{RST})
NetR30_2: R30.2 U3.59(RBIAS)
NetR34_1: R34.1 U7.4(B)
NetR36_2: R36.2 U8.3(A)

Not connected (* = marked no-connect by the designer): J5 7 9; J11 7* 8*; U3 2(PD1/AIN14/C1O/I2C7SDA/SSI2XDAT0/T0CCP1)* 5(PQ0/EPI0S20/SSI3CLK)* 6(PQ1/EPI0S21/SSI3FSS)* 11(PQ2/EPI0S22/SSI3XDAT0)* 12(PE3/AIN0/U1DTR)* 13(PE2/AIN1/U1DCD)* 14(PE1/AIN2/U1DSR)* 15(PE0/AIN3/U1RTS)* 18(PK0/AIN16/EPI0S0/U4RX)* 19(PK1/AIN17/EPI0S1/U4TX)* 20(PK2/AIN18/EPI0S2/U4RTS)* 21(PK3/AIN19/EPI0S3/U4CTS)* 22(PC7/C0-/EPI0S4/U5TX)* 23(PC6/C0+/EPI0S5/U5RX)* 24(PC5/C1+/EPI0S6/RTCCLK/U7TX)* 25(PC4/C1-/EPI0S7/U7RX)* 27(PQ3/EPI0S23/SSI3XDAT1)* 29(PH0/EPI0S0/U0RTS)* 30(PH1/EPI0S1/U0CTS)* 31(PH2/EPI0S2/U0DCD)* 32(PH3/EPI0S3/U0DSR)* 41(PA7/EPI0S9/I2C6SDA/SSI0XDAT3/T3CCP1/U2TX/USB0EPEN/USB0PFLT)* 42(PF0/EN0LED0/M0PWM0/SSI3XDAT1/TRD2)* 43(PF1/EN0LED2/M0PWM1/SSI3XDAT0/TRD1)* 44(PF2/M0PWM2/SSI3FSS/TRD0)* 45(PF3/M0PWM3/SSI3CLK/TRCLK)* 46(PF4/EN0LED1/M0FAULT0/SSI3XDAT2/TRD3)* 49(PG0/EN0PPS/EPI0S11/I2C1SCL/M0PWM4)* 50(PG1/EPI0S10/I2C1SDA/M0PWM5)* 53(EN0RXIN)* 54(EN0RXIP)* 56(EN0TXON)* 57(EN0TXOP)* 65(~{HIB})* 67(XOSC1)* 71(PM7/T5CCP1/TMPR0/U0RI)* 72(PM6/T5CCP0/TMPR1/U0DSR)* 73(PM5/T4CCP1/TMPR2/U0DCD)* 74(PM4/T4CCP0/TMPR3/U0CTS)* 75(PM3/EPI0S12/T3CCP1)* 76(PM2/EPI0S13/T3CCP0)* 77(PM1/EPI0S14/T2CCP1)* 78(PM0/EPI0S15/T2CCP0)* 81(PL0/EPI0S16/I2C2SDA/M0FAULT3/USB0D0)* 82(PL1/EPI0S17/I2C2SCL/PHA0/USB0D1)* 83(PL2/C0O/EPI0S18/PHB0/USB0D2)* 84(PL3/C1O/EPI0S19/IDX0/USB0D3)* 85(PL4/EPI0S26/T0CCP0/USB0D4)* 86(PL5/EPI0S33/T0CCP1/USB0D5)* 91(PB2/EPI0S27/I2C0SCL/T5CCP0/USB0STP)* 92(PB3/EPI0S28/I2C0SDA/T5CCP1/USB0CLK)* 102(P/DIVSCLK/U1RX)* 103(PP2/EPI0S29/U0DTR/USB0NXT)* 104(PP3/EPI0S30/RTCCLK/U0DCD/U1CTS/USB0DIR)* 105(PP4/U0DSR/U3RTS/USB0D7)* 106(PP5/I2C2SCL/U3CTS/USB0D6)* 107(PN0/U1RTS)* 108(PN1/U1CTS)* 109(PN2/EPI0S29/U1DCD/U2RTS)* 110(PN3/EPI0S30/U1DSR/U2CTS)* 111(PN4/EPI0S34/I2C2SDA/U1DTR/U3RTS)* 112(PN5/EPI0S35/I2C2SCL/U1RI/U3CTS)* 116(PJ0/EN0PPS/U3RX)* 117(PJ1/U3TX)* 118(PP0/C2+/SSI3XDAT2/U6RX)* 119(PP1/C2-/SSI3XDAT3/U6TX)* 120(PB5/AIN11/I2C5SDA/SSI1CLK/U0RTS)* 121(PB4/AIN10/I2C5SCL/SSI1FSS/U0CTS)* 123(PE4/AIN9/SSI1XDAT0/U1RI)* 124(PE5/AIN8/SSI1XDAT1)* 125(PD4/AIN7/SSI1XDAT2/T3CCP0/U2RX)* 126(PD5/AIN6/SSI1XDAT3/T3CCP1/U2TX)* 127(PD6/AIN5/SSI2XDAT3/T4CCP0/U2RTS/USB0EPEN)* 128(PD7/AIN4/NMI/SSI2XDAT2/T4CCP1/U2CTS/USB0PFLT)*; U5 4(D2+) 5(D2-) 6(NC) 7(NC); U6 3(NC)*

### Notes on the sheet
- EMULATION  CIRCUIT

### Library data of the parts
C17-C19 C26 C28 C40 C41 = CMP-0085850-1: CAP, CERM, 0.1 µF, 16 V,+/- 10%, X7R, 0402; Manufacturer: Walsin; Alternate PartNumber: C1005X5R1A104K050BA; Polarized: N; Value: 0.1uF; U/M: EA; Cap_F: 100nF; VDC_V: 16V; TaMin_C: -55°C; TaMax_C: 125°C; Cap_Case: 0402; SizeAreaWB_mm2: 3; SizeZ_mm: 0.6; SizeX_mm: 1; SizeY_mm: 0.5; AEC Category: Q200
C20 C22 C24 C29-C31 C35 = CMP-0085842-1: CAP, CERM, 0.01 µF, 50 V,+/- 10%, X7R, 0402; Manufacturer: Walsin; Alternate PartNumber: C1005X7R1C103K050BA; Polarized: N; Value: 0.01uF; U/M: EA; Cap_F: 10nF; VDC_V: 50V; TaMin_C: -55°C; TaMax_C: 125°C; Cap_Case: 0402; AEC Category: Q200; SizeAreaWB_mm2: 3; SizeZ_mm: 0.6; SizeX_mm: 1; SizeY_mm: 0.5
C21 C23 = CMP-0085851-1: CAP, CERM, 22 pF, 50 V,+/- 5%, C0G/NP0, 0402; Manufacturer: Walsin; Alternate PartNumber: GRM1555C1H220FA01D; Polarized: N; Value: 22pF; U/M: EA; VDC_V: 50V; TaMin_C: -55°C; TaMax_C: 125°C; Cap_Case: 0402; AEC Category: Q200; SizeAreaWB_mm2: 3; SizeZ_mm: 0.6; SizeX_mm: 1; SizeY_mm: 0.5
C25 C27 C34 C36 C39 = CMP-0085848-1: CAP, CERM, 1 µF, 25 V,+/- 10%, X5R, 0402; Manufacturer: Samsung Electro-Mechanics; Alternate PartNumber: C1005X5R1E105K050BC; Polarized: N; Value: 1uF; U/M: EA; VDC_V: 25V; TaMin_C: -55°C; TaMax_C: 85°C; Cap_Case: 0402; AEC Category: Q200; SizeArea_mm2: 0.5; SizeAreaWB_mm2: 3; SizeX_mm: 1; SizeZ_mm: 0.6
C32 C33 C38 = CMP-0006758-5: CAP, CERM, 0.1 uF, 25 V, +/- 10%, X5R, 0603; PartNumber: 06033D104KAT2A; Manufacturer: AVX; Alternate PartNumber: 0603B104K250CT; Alternate Manufacturer: Walsin; Polarized: N; CompType: Capacitor; Value: 0.1uF; U/M: EA; Cap_F: 100nF; ESR_ohm: 0.048; Value1: 0.048 ohm; VDC_V: 25V; IRMS_A: 5.3dA; TaMin_C: -55°C; TaMax_C: 85°C; AEC Category: Q200; SizeAreaWB_mm2: 4.68; SizeZ_mm: 1; SizeX_mm: 1.6; SizeY_mm: 0.8; SizeArea_mm2: 1.28
C37 = CMP-0006275-2: CAP, CERM, 2.2 uF, 16 V, +/- 10%, X5R, 0402; PartNumber: C1005X5R1C225K050BC; Manufacturer: TDK; Alternate PartNumber: CL05A225KA5NUNC; Alternate Manufacturer: SAMSUNG; Polarized: N; CompType: Capacitor; Value: 2.2uF; U/M: EA; Cap_F: 2.2µF; Value1: Unknown; VDC_V: 16V; TaMin_C: -55°C; TaMax_C: 85°C; AEC Category: Q200; SizeAreaWB_mm2: 3; SizeZ_mm: 0.6; SizeX_mm: 1; SizeY_mm: 0.5
D1 = CMP-0002871-1: LED, Red, SMD; Manufacturer: Everlight; PartNumber: 19-217/R6C-AL1M2VY/3T; Alternate Manufacturer: Rohm; Alternate PartNumber: SML-311UTT86; Type: AlInGaP; Vf_V: 1.8V; Io_A: 2mA; Value1: W; U/M: EA
D2 = CMP-0002834-1: LED, Green, SMD; Manufacturer: Lumex; PartNumber: SML-LX0603GW-TR; Alternate Manufacturer: Everlight; Alternate PartNumber: 19-217/G7C-AN1P2/3T; Vf_V: 2.2V; Io_A: 20mA; Tjmax_C: 85°C; Value1: W; U/M: EA
D3 = CMP-0002892-2: LED, Yellow, SMD; Manufacturer: Wurth Elektronik; PartNumber: 150060YS75000; Alternate Manufacturer: Everlight; Alternate PartNumber: 19-217/G7C-AN1P2/3T; Type: AlInGaP; Vf_V: 2V; Io_A: 20mA; Value1: W; U/M: EA
J4 = CMP-0054806-2: Header, 2.54 mm, 5x2, Gold, TH; PartNumber: 61301021121; Manufacturer: Wurth Elektronik; Alternate Manufacturer: ----; Green_Lifecycle: Active; Green_REACh: Passed; Cert_UL: Y; Current_A: 3A; Gender: Male; Pitch_mm: 2.54; Row_Count: 2; Shrouded: N; Voltage_V: 250V
J5 = CMP-0075101-1: Footprint for Tag-Connect TC2050 No-Legs cables; PartNumber: TC2050-IDC-NL-FP; CompType: Receptacle; Note: Footprint only, to mate with Tag-Connect TC2050 No-Legs cables; CT: False
J6 = CMP-0055311-1: Receptacle, USB 2.0, Micro B, 5 Position, R/A, SMT; PartNumber: 1051640001; Manufacturer: Molex; Alternate Manufacturer: ----; Pitch_mm: 0.65; Gender: Female; ContactFinish: Gold; Current_A: 1.8A; Voltage_V: 30V; Cert_UL: Y; CNHeader: FALSE; CT: TRUE
J7 J8 = CMP-0075533-1: Header, 1.27 mm, 5x2, Gold, TH; PartNumber: FTSH-105-01-F-D-K; Manufacturer: Samtec; Alternate Manufacturer: ----; Pitch_mm: 1.27; Gender: Male; Green_REACh: Passed; CT: False; Shrouded: Y; Green_Lifecycle: Active; Row_Count: 2
J9 J10 = CMP-0054796-1: Header, 2.54 mm, 3x1, Gold, TH; PartNumber: 61300311121; Manufacturer: Wurth Elektronik; Alternate Manufacturer: ----; CNHeader: TRUE; Green_Lifecycle: Active; Green_REACh: Passed; CT: FALSE
J11 = CMP-0055564-1: Header, 1.27mm, 7x2, Gold, SMT; PartNumber: FTSH-107-01-F-DV; Manufacturer: Samtec; Alternate Manufacturer: ----; Pitch_mm: 1.27; Gender: Male; Shrouded: N; Row_Count: 2; Current_A: 3.3A; Cert_UL: Y; Green_Lifecycle: Active; Green_REACh: Passed; CNHeader: TRUE; CT: FALSE
L5 L6 = CMP-0003309-1: Ferrite Bead, 10 ohm @ 100 MHz, 1 A, 0402; PartNumber: BLM15AG100SN1D; Manufacturer: MuRata; Alternate PartNumber: ----; Value: 10 ohm; Imax_A: 1A; DCR_ohm: 0.025; Value1: 0.025 ohm; ZTyp@100MHz_Ohm: 10; SizeAreaWB_mm2: 3; SizeZ_mm: 0.6; SizeX_mm: 1; SizeY_mm: 0.5
Q1 = CMP-0000755-1: MOSFET, N-CH, 50 V, 0.22 A, SOT-23; Manufacturer: Fairchild Semiconductor; Alternate Manufacturer: ON; Alternate PartNumber: BSS138LT1G; U/M: EA; ChType: N; Value: 50V; Rdson45_ohm: 6; Value2: 1.7 nC; QgTyp_nC: 1.7; Vgs_V: 20V; IdsMax_A: 2.2dA; SizeZ_mm: 1.1; SizeX_mm: 2.5; SizeY_mm: 3; SizeArea_mm2: 7.5; AEC Category: Q101; SizeAreaWB_mm2: 14
R5 R7 R9-R13 = CMP-0026696-1: RES, 33.0, 1%, 0.1 W, 0402; PartNumber: ERJ-2RKF33R0X; Manufacturer: Panasonic; Alternate Manufacturer: YAGEO; Alternate PartNumber: RC0402FR-0733RL; Value: 33.0; Res_ohm: 33; Value_Code: 33R0; Power_W: 100mW; Value2: 0.1W; VDC_V: 50V; TempCo: 100 ppm/C; U/M: EA; AEC Category: Q200; SizeX_mm: 1; SizeY_mm: 0.5; SizeZ_mm: 0.6
R6 = CMP-0026992-2: RES, 0, 5%, 0.063 W, 0402; PartNumber: ERJ-2GE0R00X; Manufacturer: Panasonic; Alternate Manufacturer: YAGEO; Alternate PartNumber: RC0402JR-070RL; CompType: Resistor; Value: 0; Value_Code: 0000; Power_W: 63mW; Value2: 0.063W; VDC_V: 50V; TempCo: 600 ppm/C; EIA_Code: E24; U/M: EA; SizeX_mm: 1; SizeY_mm: 0.5; SizeZ_mm: 0.6; AEC Category: Q200
R8 = CMP-0026824-3: RES, 100, 5%, 0.063 W, AEC-Q200 Grade 0, 0402; PartNumber: CRCW0402100RJNED; Manufacturer: Vishay-Dale; Alternate Manufacturer: YAGEO; Alternate PartNumber: RC0402JR-07100RL; CompType: Resistor; Value: 100; Value_Code: 100R; Power_W: 63mW; Value2: 0.063W; VDC_V: 50V; TempCo: 200 ppm/C; EIA_Code: E24; AEC Category: Q200; AEC Qualified: Y; AEC Grade: 0; SizeX_mm: 1; SizeY_mm: 0.5; SizeZ_mm: 0.6
R14 = CMP-0026823-3: RES, 100 k, 5%, 0.063 W, AEC-Q200 Grade 0, 0402; PartNumber: CRCW0402100KJNED; Manufacturer: Vishay-Dale; Alternate Manufacturer: YAGEO; Alternate PartNumber: RC0402JR-07100KL; CompType: Resistor; Value: 100k; Power_W: 63mW; Value2: 0.063W; VDC_V: 50V; TempCo: 200 ppm/C; EIA_Code: E24; SizeX_mm: 1; SizeY_mm: 0.5; SizeZ_mm: 0.6; AEC Qualified: Y; AEC Category: Q200; AEC Grade: 0
R15 = CMP-0026905-2: RES, 330 k, 5%, 0.063 W, AEC-Q200 Grade 0, 0402; PartNumber: CRCW0402330KJNED; Manufacturer: Vishay-Dale; Alternate Manufacturer: YAGEO; Alternate PartNumber: RC0402JR-07330KL; CompType: Resistor; Value: 330k; Power_W: 63mW; Value2: 0.063W; VDC_V: 50V; TempCo: 200 ppm/C; EIA_Code: E24; AEC Category: Q200; AEC Qualified: Y; AEC Grade: 0; SizeX_mm: 1; SizeY_mm: 0.5; SizeZ_mm: 0.6
R16 = CMP-0026877-2: RES, 220 k, 5%, 0.063 W, AEC-Q200 Grade 0, 0402; PartNumber: CRCW0402220KJNED; Manufacturer: Vishay-Dale; Alternate Manufacturer: YAGEO; Alternate PartNumber: RC0402JR-07220KL; CompType: Resistor; Value: 220k; Power_W: 63mW; Value2: 0.063W; VDC_V: 50V; TempCo: 200 ppm/C; EIA_Code: E24; AEC Category: Q200; AEC Qualified: Y; AEC Grade: 0; SizeX_mm: 1; SizeY_mm: 0.5; SizeZ_mm: 0.6
R17 R26 = CMP-0026825-5: RES, 10 k, 5%, 0.063 W, AEC-Q200 Grade 0, 0402; PartNumber: CRCW040210K0JNED; Manufacturer: Vishay-Dale; Alternate Manufacturer: YAGEO; Alternate PartNumber: RC0402JR-0710KL; Value: 10k; Value_Code: 10k0; Power_W: 63mW; Value2: 0.063W; VDC_V: 50V; TempCo: 200 ppm/C; EIA_Code: E24; SizeX_mm: 1; SizeY_mm: 0.5; SizeZ_mm: 0.6; AEC Qualified: Y; AEC Category: Q200; AEC Grade: 0
R18 R19 = CMP-0025756-4: RES, 220, 5%, 0.1 W, AEC-Q200 Grade 0, 0603; PartNumber: CRCW0603220RJNEA; Manufacturer: Vishay-Dale; Alternate Manufacturer: YAGEO; Alternate PartNumber: RC0603JR-07220RL; Value: 220; Value_Code: 220R; Power_W: 100mW; Value2: 0.1W; VDC_V: 75V; TempCo: 200 ppm/C; EIA_Code: E24; AEC Category: Q200; AEC Qualified: Y; AEC Grade: 0; SizeX_mm: 1.6; SizeY_mm: 0.8; SizeZ_mm: 1; SizeArea_mm2: 1.28
R20 = CMP-0025765-4: RES, 270, 5%, 0.1 W, AEC-Q200 Grade 0, 0603; PartNumber: CRCW0603270RJNEA; Manufacturer: Vishay-Dale; Alternate Manufacturer: YAGEO; Alternate PartNumber: RC0603JR-07270RL; CompType: Resistor; Value: 270; Value_Code: 270R; Power_W: 100mW; Value2: 0.1W; VDC_V: 75V; TempCo: 200 ppm/C; EIA_Code: E24; SizeX_mm: 1.6; SizeY_mm: 0.8; SizeZ_mm: 1; SizeArea_mm2: 1.28; AEC Qualified: Y; AEC Category: Q200; AEC Grade: 0
R21 = CMP-0026656-1: RES, 100, 1%, 0.1 W, 0402; PartNumber: ERJ-2RKF1000X; Manufacturer: Panasonic; Alternate Manufacturer: YAGEO; Alternate PartNumber: RC0402FR-07100RL; CompType: Resistor; Value: 100; Value_Code: 100R; Power_W: 100mW; Value2: 0.1W; VDC_V: 50V; TempCo: 100 ppm/C; EIA_Code: E96; U/M: EA; SizeX_mm: 1; SizeY_mm: 0.5; SizeZ_mm: 0.6; AEC Category: Q200
R22-R25 R28 R31 R35 R37 = CMP-0026852-3: RES, 1.0 k, 5%, 0.063 W, AEC-Q200 Grade 0, 0402; PartNumber: CRCW04021K00JNED; Manufacturer: Vishay-Dale; Alternate Manufacturer: YAGEO; Alternate PartNumber: RC0402JR-071KL; Value: 1.0k; Res_ohm: 1k; Value_Code: 1k00; Power_W: 63mW; Value2: 0.063W; VDC_V: 50V; TempCo: 200 ppm/C; EIA_Code: E24; SizeX_mm: 1; SizeY_mm: 0.5; SizeZ_mm: 0.6; AEC Qualified: Y; AEC Category: Q200; AEC Grade: 0
R27 = CMP-0025698-4: RES, 100 k, 5%, 0.1 W, AEC-Q200 Grade 0, 0603; PartNumber: CRCW0603100KJNEA; Manufacturer: Vishay-Dale; Alternate Manufacturer: YAGEO; Alternate PartNumber: RC0603JR-07100KL; CompType: Resistor; Value: 100k; Power_W: 100mW; Value2: 0.1W; VDC_V: 75V; TempCo: 200 ppm/C; EIA_Code: E24; AEC Category: Q200; AEC Qualified: Y; AEC Grade: 0; SizeX_mm: 1.6; SizeY_mm: 0.8; SizeZ_mm: 1; SizeArea_mm2: 1.28
R29 = CMP-0025951-3: RES, 100, 1%, 0.063 W, AEC-Q200 Grade 0, 0402; PartNumber: CRCW0402100RFKED; Manufacturer: Vishay-Dale; Alternate Manufacturer: YAGEO; Alternate PartNumber: RC0402FR-07100RL; CompType: Resistor; Value: 100; Value_Code: 100R; Power_W: 63mW; Value2: 0.063W; VDC_V: 50V; TempCo: 100 ppm/C; EIA_Code: E96; AEC Category: Q200; AEC Qualified: Y; AEC Grade: 0; SizeX_mm: 1; SizeY_mm: 0.5; SizeZ_mm: 0.6
R30 = CMP-0022457-4: RES, 4.87 k, 1%, 0.1 W, AEC-Q200 Grade 0, 0603; PartNumber: CRCW06034K87FKEA; Manufacturer: Vishay-Dale; Alternate Manufacturer: YAGEO; Alternate PartNumber: RC0603FR-074K87L; CompType: Resistor; Value: 4.87k; Value_Code: 4k87; Power_W: 100mW; Value2: 0.1W; VDC_V: 75V; TempCo: 100 ppm/C; EIA_Code: E96; AEC Category: Q200; AEC Qualified: Y; AEC Grade: 0; SizeX_mm: 1.6; SizeY_mm: 0.8; SizeZ_mm: 1; SizeArea_mm2: 1.28
R32 = CMP-0026946-3: RES, 51, 5%, 0.063 W, AEC-Q200 Grade 0, 0402; PartNumber: CRCW040251R0JNED; Manufacturer: Vishay-Dale; Alternate Manufacturer: YAGEO; Alternate PartNumber: RC0402JR-0751RL; CompType: Resistor; Value: 51; Value_Code: 51R0; Power_W: 63mW; Value2: 0.063W; VDC_V: 50V; TempCo: 200 ppm/C; EIA_Code: E24; AEC Category: Q200; AEC Qualified: Y; AEC Grade: 0; SizeX_mm: 1; SizeY_mm: 0.5; SizeZ_mm: 0.6
R33 = CMP-0026823-3: RES, 100 k, 5%, 0.063 W, AEC-Q200 Grade 0, 0402; PartNumber: CRCW0402100KJNED; Manufacturer: Vishay-Dale; Alternate Manufacturer: YAGEO; Alternate PartNumber: RC0402JR-07100KL; Value: 100k; Power_W: 63mW; Value2: 0.063W; VDC_V: 50V; TempCo: 200 ppm/C; EIA_Code: E24; SizeX_mm: 1; SizeY_mm: 0.5; SizeZ_mm: 0.6; AEC Qualified: Y; AEC Category: Q200; AEC Grade: 0
R34 R36 = CMP-0026696-1: RES, 33.0, 1%, 0.1 W, 0402; PartNumber: ERJ-2RKF33R0X; Manufacturer: Panasonic; Alternate Manufacturer: YAGEO; Alternate PartNumber: RC0402FR-0733RL; Value: 33.0; Res_ohm: 33; Value_Code: 33R0; Power_W: 100mW; Value2: 0.1W; VDC_V: 50V; TempCo: 100 ppm/C; U/M: EA; SizeX_mm: 1; SizeY_mm: 0.5; SizeZ_mm: 0.6; AEC Category: Q200
R38 R39 = CMP-0025787-4: RES, 33, 5%, 0.1 W, AEC-Q200 Grade 0, 0603; PartNumber: CRCW060333R0JNEA; Manufacturer: Vishay-Dale; Alternate Manufacturer: YAGEO; Alternate PartNumber: RC0603JR-0733RL; Value: 33; Value_Code: 33R0; Power_W: 100mW; Value2: 0.1W; VDC_V: 75V; TempCo: 200 ppm/C; EIA_Code: E24; SizeX_mm: 1.6; SizeY_mm: 0.8; SizeZ_mm: 1; SizeArea_mm2: 1.28; AEC Qualified: Y; AEC Category: Q200; AEC Grade: 0
SW1 = CMP-0002328-1: Switch, SPST, 0.05 A, 12 VDC, SMD; PartNumber: 1188E-1K2-V-TR; Manufacturer: Diptronics; Alternate Manufacturer: ----; VDC_V: 12V; PositionCount: 1; CurrentRating_mA: 50A; SizeAreaWB_mm2: 53.9; SizeArea_mm2: 27.3; SizeX_mm: 7.8; SizeY_mm: 3.5
TP1 = CMP-0078143-2: TEST POINT.  No entry in BOM.
U3 = CMP-0029864-2: Tiva C Series Microcontroller, 1024 KB Flash, 256 KB SRAM, 12 Bit, 20 Channels, -40 to 85 degC, 128-Pin TQFP (PDT), Green (RoHS & no Sb/Br), Tape and Reel; Manufacturer: Texas Instruments; Alternate PartNumber: ----; CompType: IC; ADC Channels: 20; CPU: ARM Cortex-M4; Flash: 1024 KB; ADC Resolution: 12 Bits; Max Speed: 120 MHz; SRAM: 256 KB; SizeAreaWB_mm2: 324.0; SizeArea_mm2: 256.0; SizeX_mm: 16.0; SizeZ_mm: 1.2
U4 = CMP-0051039-3: Single-Bit Dual-Supply Bus Transceiver with Configurable Voltage Translation and 3-State Outputs, DCK0006A, LARGE T&R; Alternate PartNumber: SN74LVC1T45DCKT; Manufacturer: Texas Instruments; Generic Part Number: SN74LVC1T45; SizeArea_mm2: 4.2; SizeAreaWB_mm2: 9.3; SizeX_mm: 2.1; SizeY_mm: 2; SizeZ_mm: 1.1; CompType: IC; Output Type: CMOS; Bits(#): 1; Input Type: CMOS/TTL; Technology Family: LVC; Schmitt Trigger: No; 3-State Output: Yes; VCC(Max)(V): 5.5; Sub-Family: Dual Supply Translator; Rating: Catalog; Output Drive (IOL/IOH)(Max)(mA): 32/-32; ICC @ Nom Voltage(Max)(mA): 0.004; VCC(Min)(V): 1.65; F @ Nom Voltage(Max)(Mhz): 150; Logic: True; Voltage(Nom)(V): 1.8,2.5,3.3,5; tpd @ Nom Voltage(Max)(ns): 15.5,8,5.8,4.4; AEC Category: Q200; AEC Qualified: N
U5 = CMP-0043121-2: ESD Solution for High-Speed Differential Interface, 4 Channels, -40 to +85 degC,10-pin SON (DQA), Green (RoHS & no Sb/Br); Manufacturer: Texas Instruments; Alternate PartNumber: ----; 1394 / Firewire: TRUE; Breakdown Voltage(Min)(V): 9; Differential Capacitance(pF): 0.05; IEC 61000-4-2 Contact(+/- kV): 8; IO Capacitance(Typ)(pF): 0.8; IO Leakage Current(nA): 10
U6 = CMP-0033095-1: Precision Micropower Shunt Voltage Reference, 0.2% accuracy, 2.5 V, 15 ppm / degC, 15 mA, -40 to 85 degC, 3-pin SOT-23 (DBZ), Green (RoHS & no Sb/Br); Manufacturer: Texas Instruments; Alternate PartNumber: ----; Initial Accuracy @ 25/deg C(%): 0.2; Iout/Iz(Max)(mA): 15; Min Iz for Regulation(uA): 75; Rating: Catalog; Temp Coeff(Max)(ppm/ degree C): 100; VO(V): 2.5
U7 U8 = CMP-0051039-3: Single-Bit Dual-Supply Bus Transceiver with Configurable Voltage Translation and 3-State Outputs, DCK0006A, LARGE T&R; Alternate PartNumber: SN74LVC1T45DCKT; Manufacturer: Texas Instruments; Generic Part Number: SN74LVC1T45; CompType: IC; Output Type: CMOS; Bits(#): 1; Input Type: CMOS/TTL; Technology Family: LVC; Schmitt Trigger: No; 3-State Output: Yes; VCC(Max)(V): 5.5; Sub-Family: Dual Supply Translator; Rating: Catalog; Output Drive (IOL/IOH)(Max)(mA): 32/-32; ICC @ Nom Voltage(Max)(mA): 0.004; VCC(Min)(V): 1.65; F @ Nom Voltage(Max)(Mhz): 150; Logic: True; Voltage(Nom)(V): 1.8,2.5,3.3,5; tpd @ Nom Voltage(Max)(ns): 15.5,8,5.8,4.4; AEC Category: Q200; AEC Qualified: N; SizeAreaWB_mm2: 9.3; SizeArea_mm2: 4.2; SizeX_mm: 2.1; SizeY_mm: 2; SizeZ_mm: 1.1
Y1 = CMP-0004648-3: Crystal, 16 MHz, 18 pF, SMD; PartNumber: ABM3-16.000MHZ-D2Y-T; Manufacturer: Abracon Corporation; Alternate Manufacturer: ----; TaMin_C: -40°C; TaMax_C: 85°C; Frequency Stability: +/-30ppm

## Sheet MCU014B_D1_EVM_Hardware.SchDoc
size 558 x 431 mm; Date: Not shown in title block; ApprovedBy: Not shown in title block; CheckedBy: Not shown in title block; Author: Not shown in title block; CompanyName: Not shown in title block; DrawnBy: Vince Rodriguez; Engineer: Not shown in title block; Organization: Not shown in title block; Address1: Not shown in title block; Address2: Not shown in title block; Address3: Not shown in title block; Address4: Not shown in title block; DocumentNumber: 7; Revision: Use project parameter SCH_Rev; SheetNumber: 7; SheetTotal: 7; PageSetup: Record=PageOptions¦CenterHorizontal=True¦CenterVertical=True¦PrintScale=1.00¦XCorrection=1.00¦YCorrection=1.00¦PrintKind=0¦BorderSize=5000000¦LeftOffset=0¦BottomOffset=0¦Orientation=2¦PaperLength=1000¦PaperWidth=1000¦Scale=100¦PaperSource=15¦PrintQuality=600¦MediaType=1¦DitherType=10¦PaperKind=Letter¦PrintScaleMode=1
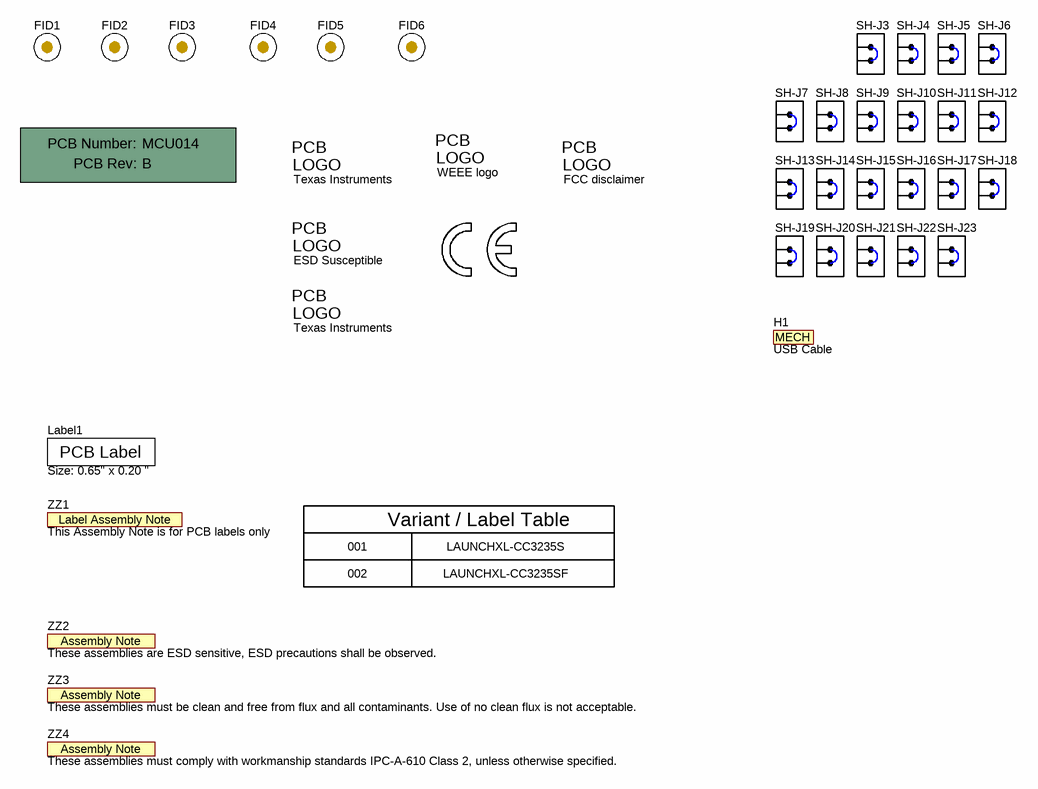
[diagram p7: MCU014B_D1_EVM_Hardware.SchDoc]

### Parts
FID1  CMP-0077181-1  [Fiducial10-20]  (value not drawn)  (no BOM)
FID2  CMP-0077181-1  [Fiducial10-20]  (value not drawn)  (no BOM)
FID3  CMP-0077181-1  [Fiducial10-20]  (value not drawn)  (no BOM)
FID4  CMP-0077181-1  [Fiducial10-20]  (value not drawn)  (no BOM)
FID5  CMP-0077181-1  [Fiducial10-20]  (value not drawn)  (no BOM)
FID6  CMP-0077181-1  [Fiducial10-20]  (value not drawn)  (no BOM)
H1  USB Cable  (mechanical)
Label1  Note: Size: 0.65" x 0.20 "  [Label_650x200]  (hidden comment: CMP-0003625-1)
Logo1  WEEE logo  [WEEE_Minimum]  (no BOM)
Logo2  Texas Instruments  [TI_Stacked_Overlay_Small]  (no BOM)
Logo3  FCC disclaimer  [FCC_disclaimer_stacked]  (no BOM)
Logo4  ESD Susceptible  [ESD_Overlay_Medium]  (no BOM)
Logo5  CMP-0074844-1  [CE_Mark_5mm]  (value not drawn)  (no BOM)
Logo6  Texas Instruments  [TI_Symbol_Overlay_Small]  (no BOM)
PCB1  Printed Circuit Board  (value not drawn)  (mechanical)
SH-J3  CMP-0003761-1  [Wurth_60900213421]  (value not drawn)
SH-J4  CMP-0003761-1  [Wurth_60900213421]  (value not drawn)
SH-J5  CMP-0003761-1  [Wurth_60900213421]  (value not drawn)
SH-J6  CMP-0003761-1  [Wurth_60900213421]  (value not drawn)
SH-J7  CMP-0003761-1  [Wurth_60900213421]  (value not drawn)
SH-J8  CMP-0003761-1  [Wurth_60900213421]  (value not drawn)
SH-J9  CMP-0003761-1  [Wurth_60900213421]  (value not drawn)
SH-J10  CMP-0003761-1  [Wurth_60900213421]  (value not drawn)
SH-J11  CMP-0003761-1  [Wurth_60900213421]  (value not drawn)
SH-J12  CMP-0003761-1  [Wurth_60900213421]  (value not drawn)
SH-J13  CMP-0003761-1  [Wurth_60900213421]  (value not drawn)
SH-J14  CMP-0003761-1  [Wurth_60900213421]  (value not drawn)
SH-J15  CMP-0003761-1  [Wurth_60900213421]  (value not drawn)
SH-J16  CMP-0003761-1  [Wurth_60900213421]  (value not drawn)
SH-J17  CMP-0003761-1  [Wurth_60900213421]  (value not drawn)
SH-J18  CMP-0003761-1  [Wurth_60900213421]  (value not drawn)
SH-J19  CMP-0003761-1  [Wurth_60900213421]  (value not drawn)
SH-J20  CMP-0003761-1  [Wurth_60900213421]  (value not drawn)
SH-J21  CMP-0003761-1  [Wurth_60900213421]  (value not drawn)
SH-J22  CMP-0003761-1  [Wurth_60900213421]  (value not drawn)
SH-J23  CMP-0003761-1  [Wurth_60900213421]  (value not drawn)
ZZ1  This Assembly Note is for PCB labels only  [AssemblyNoteLabel]  (no BOM)
ZZ2  These assemblies are ESD sensitive, ESD precautions shall be observed.  [AssemblyNote]  (no BOM)
ZZ3  These assemblies must be clean and free from flux and all contaminants. Use of no clean flux is not acceptable.  [AssemblyNote]  (no BOM)
ZZ4  These assemblies must comply with workmanship standards IPC-A-610 Class 2, unless otherwise specified.  [AssemblyNote]  (no BOM)

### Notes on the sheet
- Variant / Label Table
- 001
- 002
- LAUNCHXL-CC3235S
- LAUNCHXL-CC3235SF

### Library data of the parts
FID1-FID6 = CMP-0077181-1: Fiducial mark.  There is nothing to buy or mount.
H1 = CMP-0077983-1: Cable, USB-A to micro USB-B, 0.3 m; Manufacturer: Assman WSW; PartNumber: AK67421-0.3-VM; Alternate Manufacturer: ----; Alternate PartNumber: GLJ-C4-1306
Label1 = CMP-0003625-1: Thermal Transfer Printable Labels, 0.650" W x 0.200" H - 10,000 per roll; Manufacturer: Brady; PartNumber: THT-14-423-10; Alternate Manufacturer: ----; CompType: Label
Logo1 = CMP-0074769-1
Logo2 Logo6 = CMP-0074838-1: Texas Instrument Corporate Signature; SymbolCreator: a0412235; Library Reference: Logo; Lib Reference: TI_Logo
Logo3 = CMP-0074847-1: FCC_disclaimer; Library Reference: Logo
Logo4 = CMP-0074840-1: ESD Susceptible Symbol; SymbolCreator: a0412235; Library Reference: Logo; Lib Reference: ESD_Susceptible
Logo5 = CMP-0074844-1: CE Mark; SymbolCreator: a0412235
PCB1 = CMP-0003618-2: Manufacturer: Any; PartNumber: MCU014; Alternate Manufacturer: ----; CompType: PCB
SH-J3-SH-J23 = CMP-0003761-1: Shunt, 2.54mm, Gold, Black; Manufacturer: Wurth Elektronik; PartNumber: 60900213421; Alternate Manufacturer: ----
ZZ1 = CMP-0003616-3
ZZ2 = CMP-0077236-1
ZZ3 = CMP-0077237-1
ZZ4 = CMP-0077238-1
